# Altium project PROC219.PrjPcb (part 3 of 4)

## Sheet PROC219_PluckLock.SchDoc
size 431 x 279 mm; Date: Not shown in title block; ApprovedBy: Not shown in title block; CheckedBy: Not shown in title block; Author: Not shown in title block; CompanyName: Not shown in title block; Engineer: Not shown in title block; Organization: Not shown in title block; Address1: Not shown in title block; Address2: Not shown in title block; Address3: Not shown in title block; Address4: Not shown in title block; DocumentNumber: 2; Revision: Use project parameter SCH_Rev; SheetNumber: 9; SheetTotal: 16; PageSetup: Record=PageOptions¦CenterHorizontal=True¦CenterVertical=True¦PrintScale=1.00¦XCorrection=1.00¦YCorrection=1.00¦PrintKind=0¦BorderSize=5000000¦LeftOffset=0¦BottomOffset=0¦Orientation=2¦PaperLength=1000¦PaperWidth=1000¦Scale=100¦PaperSource=15¦PrintQuality=600¦MediaType=1¦DitherType=10¦PaperKind=Letter¦PrintScaleMode=1
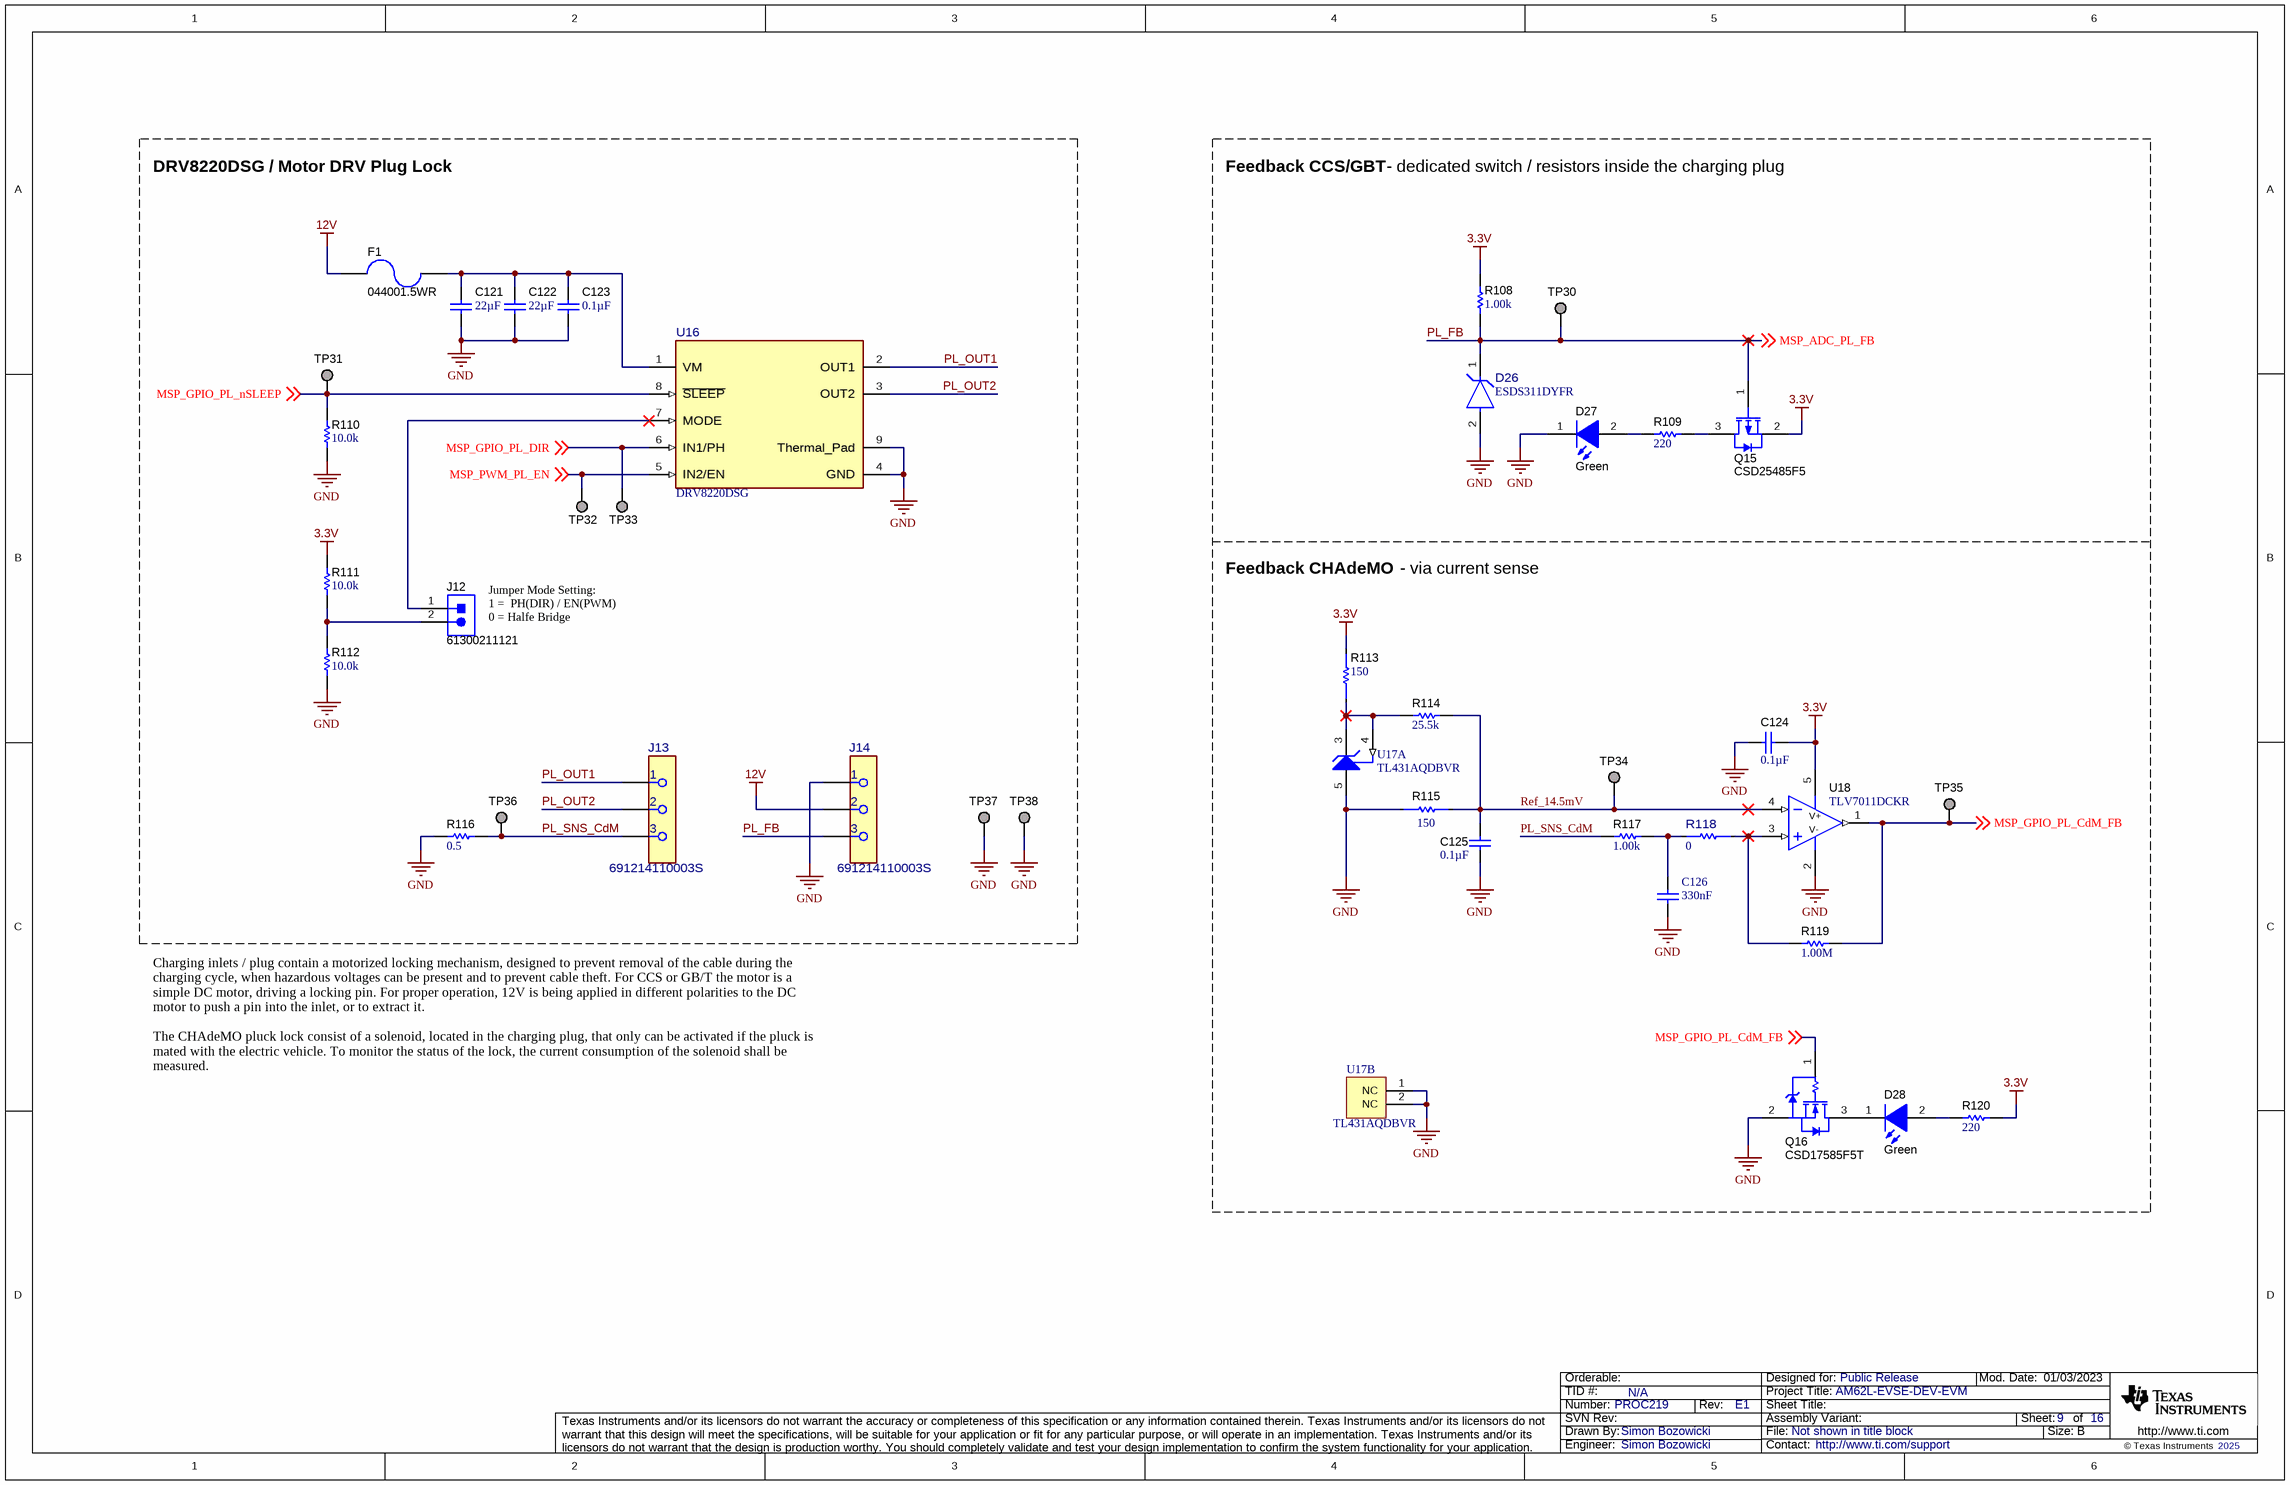
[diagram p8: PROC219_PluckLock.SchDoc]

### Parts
C121  ValueDisplayed: 22µF  [1210_270]  (hidden comment: CC1210KKX7R8BB226)
C122  ValueDisplayed: 22µF  [1210_270]  (hidden comment: CC1210KKX7R8BB226)
C123  ValueDisplayed: 0.1µF  [0402]  (hidden comment: CC0402KRX7R8BB104)
C124  ValueDisplayed: 0.1µF  [0402]  (hidden comment: CC0402KRX7R8BB104)
C125  ValueDisplayed: 0.1µF  [0402]  (hidden comment: CC0402KRX7R8BB104)
C126  value 330nF  [WCAP-CSGP_0603_L1.6W0.8H0.8_Reflow]  (hidden comment: 885012206121)
D26  ESDS311DYFR  [DYF0002A-MFG]
D27  value Green  [WL-SMCW_GREEN]  (hidden comment: 150060VS75000)
D28  value Green  [WL-SMCW_GREEN]  (hidden comment: 150060VS75000)
F1  044001.5WR  [1206]
J12  61300211121  [WURTH_61300211121]
J13  691214110003S  [FP-691214110003S_CONN_TERM_BLK_3-MFG]
J14  691214110003S  [FP-691214110003S_CONN_TERM_BLK_3-MFG]
Q15  CSD25485F5  [YJK0003A]
Q16  CSD17585F5T  [YJK0003A]
R108  ValueDisplayed: 1.00k  [0402]  (hidden comment: RC0402FR-071KL)
R109  ValueDisplayed: 220  [0402]  (hidden comment: CRCW0402220RJNED)
R110  ValueDisplayed: 10.0k  [0402]  (hidden comment: ERJ-2RKF1002X)
R111  ValueDisplayed: 10.0k  [0402]  (hidden comment: ERJ-2RKF1002X)
R112  ValueDisplayed: 10.0k  [0402]  (hidden comment: ERJ-2RKF1002X)
R113  value 150  [FP-TNPW0402150RBEED_0402-MFG]  (hidden comment: TNPW0402150RBEED)
R114  ValueDisplayed: 25.5k  [0402]  (hidden comment: CRCW040225K5FKED)
R115  value 150  [FP-TNPW0402150RBEED_0402-MFG]  (hidden comment: TNPW0402150RBEED)
R116  ValueDisplayed: 0.5  [2512]  (hidden comment: CSRN2512FKR500)
R117  ValueDisplayed: 1.00k  [0402]  (hidden comment: RC0402FR-071KL)
R118  value 0  [FP-CRG0402ZR_0402-IPC_C]  (hidden comment: CRG0402ZR)
R119  ValueDisplayed: 1.00M  [0402]  (hidden comment: RC0402FR-071ML)
R120  ValueDisplayed: 220  [0402]  (hidden comment: CRCW0402220RJNED)
TP30  TP_SM_1MM  [TP_SM_1MM]  (value not drawn)  (no BOM)
TP31  TP_SM_1MM  [TP_SM_1MM]  (value not drawn)  (no BOM)
TP32  TP_SM_1MM  [TP_SM_1MM]  (value not drawn)  (no BOM)
TP33  TP_SM_1MM  [TP_SM_1MM]  (value not drawn)  (no BOM)
TP34  TP_SM_1MM  [TP_SM_1MM]  (value not drawn)  (no BOM)
TP35  TP_SM_1MM  [TP_SM_1MM]  (value not drawn)  (no BOM)
TP36  TP_SM_1MM  [TP_SM_1MM]  (value not drawn)  (no BOM)
TP37  TP_SM_1MM  [TP_SM_1MM]  (value not drawn)  (no BOM)
TP38  TP_SM_1MM  [TP_SM_1MM]  (value not drawn)  (no BOM)
U16  PartNumber: DRV8220DSG  [DSG0008A-MFG]  (hidden comment: DRV8220DSGR)
U17  TL431AQDBVR  [DBV0005A_N]  (parts A,B of 2)
U18  TLV7011DCKR  [DCK0005A_N]

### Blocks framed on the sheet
DRV8220DSG / Motor DRV Plug Lock: C121-C123 F1 J12-J14 R110-R112 R116 TP31-TP33 TP36-TP38 U16

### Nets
3.3V: C124.2 Q15.2(S) R108.2 R111.1 R113.2 R120.2 U18.5(V+)
12V: F1.2 J14.2
GND: C121.1 C122.1 C123.2 C124.1 C125.2 C126.1 D26.2(GND) D27.1(K) J14.1 Q16.2(S) R110.2 R112.2 R115.1 R116.2 TP37.1 TP38.1 U16.4(GND) U16.9(Thermal_Pad) U17.1(NC) U17.2(NC) U17.5(ANODE) U18.2(V-)
MSP_GPIO_PL_CdM_FB: Q16.1(G) R119.2 TP35.1 U18.1(OUT) ; off-sheet MSP_GPIO_PL_CdM_FB
MSP_GPIO_PL_DIR: TP33.1 U16.6(IN1/PH) ; off-sheet MSP_GPIO_PL_DIR
MSP_GPIO_PL_nSLEEP: R110.1 TP31.1 U16.8(~{SLEEP}) ; off-sheet MSP_GPIO_PL_nSLEEP
MSP_PWM_PL_EN: TP32.1 U16.5(IN2/EN) ; off-sheet MSP_PWM_PL_EN
PL_FB: D26.1(I/O) J14.3 Q15.1(G) R108.1 TP30.1 ; off-sheet MSP_ADC_PL_FB  [also labelled MSP_ADC_PL_FB]
PL_OUT1: J13.1 U16.2(OUT1)
PL_OUT2: J13.2 U16.3(OUT2)
PL_SNS_CdM: J13.3 R116.1 R117.2 TP36.1
Ref_14.5mV: C125.1 R114.2 R115.2 TP34.1 U18.4(IN-)
NetC121_2: C121.2 C122.2 C123.1 F1.1 U16.1(VM)
NetC126_2: C126.2 R117.1 R118.2
NetD27_2: D27.2(A) R109.1
NetD28_1: D28.1(K) Q16.3(D)
NetD28_2: D28.2(A) R120.1
NetJ12_1: J12.1 U16.7(MODE)
NetJ12_2: J12.2 R111.2 R112.1
NetQ15_3: Q15.3(D) R109.2
NetR113_1: R113.1 R114.1 U17.3(CATHODE) U17.4(REF)
NetR118_1: R118.1 R119.1 U18.3(IN+)

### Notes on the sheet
- Feedback CCS/GBT
- - dedicated switch / resistors inside the charging plug
- Feedback CHAdeMO
- - via current sense
- (near J12) Jumper Mode Setting:
  1 =  PH(DIR) / EN(PWM)
  0 = Halfe Bridge
- Charging inlets / plug contain a motorized locking mechanism, designed to prevent removal of the cable during the charging cycle, when hazardous voltages can be present and to prevent cable theft. For CCS or GB/T the motor is a simple DC motor, driving a locking pin. For proper operation, 12V is being applied in different polarities to the DC motor to push a pin into the inlet, or to extract it.
  The CHAdeMO pluck lock consist of a solenoid, located in the charging plug, that only can be activated if the pluck is mated with the electric vehicle. To monitor the status of the lock, the current consumption of the solenoid shall be measured.

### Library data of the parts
C121 C122 = CMP-0082267-1: CAP, CERM, 22 µF, 25 V,+/- 10%, X7R, 1210; Manufacturer: Yageo; TaMin_C: -55°C; ESR_ohm: 1m; Polarized: N; SizeAreaWB_mm2: 14.7; Value1: 0.001 ohm; U/M: EA; Value: 22uF; TaMax_C: 125°C; SizeZ_mm: 2.7; SizeX_mm: 3.2; SizeY_mm: 2.5; Cap_Case: 1210; Value2: 25V; SizeArea_mm2: 8; AEC Category: Q200
C123-C125 = CMP-0860555-1: CAP, CERM, 0.1 µF, 25 V,+/- 10%, X7R, 0402; Manufacturer: Yageo; SizeArea_mm2: 0.5; AEC Qualified: N; SizeX_mm: 1; U/M: EA; Value: 0.1uF; TaMin_C: -55°C; VDC_V: 25V; SizeZ_mm: 0.6; Cap_F: 100nF; TaMax_C: 125°C; SizeAreaWB_mm2: 3; AEC Category: Q200
C126 = CMP-0115492-1: WCAP-CSGP Multilayer Ceramic Chip Capacitor, General Purpose, size 0603, X7R, 330nF, 50VDC; Manufacturer: Wurth Elektronik; Capacitance Tolerance: +/-10%; Dissipation Factor: 10%; Insulation Resistance: 1.5GOhm; Rated Voltage (DC): 50V; Technical Reference: X7R0603334K050DFCT10000
D26 = CMP-0122929-1: One-channel unidirectional device for 3.3V surge protection in SOD-323 package; Manufacturer: Texas Instruments; SizeZ_mm: 1mm; AEC Qualified: No; Breakdown Voltage: 4.5V; Cap_F: 4.5pF; Clamping Voltage: 6.3V; Ipp: 25A; Number Of Channels: 1; Ppk: 170W; Standoff Height: 0mm; TaMax_C: +125°C; TaMin_C: -40°C; VRWM: 3.6V
D27 D28 = CMP-0002894-2: LED, Green, SMD; Manufacturer: Wurth Elektronik; Type: AlInGaP; Value2: 2V; Io_A: 20mA; Value1: W
F1 = CMP-0003461-2: Fuse, 1.5 A, 50VAC/VDC, SMD; Manufacturer: Littelfuse; Irating_A: 1.5A; SizeAreaWB_mm2: 10.92; Interrupt_AC: 50A; VAC_V: 50V; SizeZ_mm: 1.35; SizeX_mm: 3.2; SizeY_mm: 1.6; SizeArea_mm2: 5.12; Rtyp_Ohm: 0.1759; MeltingTyp: 0.50652
J12 = CMP-0054794-2: Header, 2.54 mm, 2x1, Gold, TH; Manufacturer: Wurth Elektronik; Shrouded: N; Gender: Male; Green_REACh: Passed; Pitch_mm: 2.54; Green_Lifecycle: Active; Row_Count: 1; Cert_UL: Y
J13 J14 = CMP-0124724-1: 3 Position Wire to Board Terminal Block Horizontal with Board 0.138" (3.50mm) Through Hole; Manufacturer: Wurth; ContactFinish: Tin,Nickel; Current_A: 10A; Row_Count: 1; Voltage_V: 300V; AEC Qualified: No; Conn Gender: Female; DUT-Pitch_mm: 3.5mm; Is Female: yes; Max Wire Gauge: 16; Min Wire Gauge: 30; SizeZ_mm: 9.2mm
Q15 = CMP-0000031-3: MOSFET, P-CH, -20 V, -5.3 A, YJK0003A (PICOSTAR-3); Manufacturer: Texas Instruments; Alternate Manufacturer: None; SizeZ_mm: 0.35; SizeX_mm: 1.49; ChType: P; Vgs_V: -12V; Value2: 2.7 nC; SizeArea_mm2: 1.0877; QgTyp_nC: 2.7; SizeY_mm: 0.73; AEC Category: Q101; IdsMax_A: -5.3A; AEC Qualified: N; Value: -20V; SizeAreaWB_mm2: 4.3077; ChMode: Enhancement
Q16 = CMP-0067551-1: MOSFET, N-CH, 30 V, 5.9 A, YJK0003A (PICOSTAR-3); Alternate Manufacturer: None; Manufacturer: Texas Instruments; Rdson45_ohm: 0.033; QgTyp_nC: 1.9; SizeAreaWB_mm2: 4.3077; Vgs_V: 20V; Value1: 0.033 ohm; VdsMax_V: 30V; U/M: EA; Value: 30V; IdsMax_A: 5.9A; SizeZ_mm: 0.35; SizeX_mm: 1.49; SizeY_mm: 0.73; Value2: 1.9 nC; SizeArea_mm2: 1.0877; ChType: N; AEC Category: Q101
R108 R117 = CMP-0026725-1: RES, 1.00 k, 1%, 0.0625 W, 0402; Manufacturer: Yageo America; Power_W: 62.5mW; TempCo: 100 ppm/C; Value_Code: 1k00; U/M: EA; Value: 1.00k; EIA_Code: E96; Res_ohm: 1k; SizeX_mm: 1; SizeY_mm: 0.5; SizeZ_mm: 0.6; AEC Qualified: N; VDC_V: 50V; AEC Category: Q200
R109 R120 = CMP-0026878-3: RES, 220, 5%, 0.063 W, AEC-Q200 Grade 0, 0402; Manufacturer: Vishay-Dale; Power_W: 63mW; TempCo: 200 ppm/C; Value_Code: 220R; Value: 220; EIA_Code: E24; SizeX_mm: 1; SizeY_mm: 0.5; SizeZ_mm: 0.6; Value2: 0.063W; AEC Qualified: Y; VDC_V: 50V; AEC Category: Q200; AEC Grade: 0
R110-R112 = CMP-0026658-1: RES, 10.0 k, 1%, 0.1 W, 0402; Manufacturer: Panasonic; Power_W: 100mW; TempCo: 100 ppm/C; Value_Code: 10k0; U/M: EA; Value: 10.0k; EIA_Code: E96; Res_ohm: 10k; SizeX_mm: 1; SizeY_mm: 0.5; SizeZ_mm: 0.6; Value2: 0.1W; VDC_V: 50V; AEC Category: Q200
R113 R115 = CMP-0001694-1: 150 Ohms ±0.1% 0.063W, 1/16W Chip Resistor 0402 (1005 Metric) Anti-Sulfur, Automotive AEC-Q200, Moisture Resistant Thin Film; Manufacturer: Vishay Dale; AEC Grade: Grade 0; AEC Qualified: Yes; Power_W: 100mW; SizeZ_mm: 0.4mm; TempCo: 25ppm/°C; VDC_V: 50V
R114 = CMP-0026201-2: RES, 25.5 k, 1%, 0.063 W, AEC-Q200 Grade 0, 0402; Manufacturer: Vishay-Dale; Power_W: 63mW; TempCo: 100 ppm/C; Value_Code: 25k5; Value: 25.5k; EIA_Code: E96; SizeX_mm: 1; SizeY_mm: 0.5; SizeZ_mm: 0.6; Value2: 0.063W; AEC Qualified: Y; VDC_V: 50V; AEC Category: Q200; AEC Grade: 0
R116 = CMP-0015788-2: RES, 0.5, 1%, 2 W, 2512; Manufacturer: Stackpole Electronics Inc; Power_W: 2W; TempCo: 200 ppm/C; Value_Code: R500; U/M: EA; Value: 0.5; Res_ohm: 5d; SizeX_mm: 6.3; SizeY_mm: 3.2; SizeZ_mm: 0.71; SizeArea_mm2: 20.16; AEC Category: Q200
R118 = CMP-0095664-1: Jumper 0.063W, 1/16W Chip Resistor 0402 (1005 Metric) - Thick Film; Manufacturer: TE Connectivity; SizeZ_mm: 0.4mm; VDC_V: 50V; TempCo: 200ppm/°C; Power_W: 62.5mW; AEC Qualified: No
R119 = CMP-0026727-1: RES, 1.00 M, 1%, 0.063 W, 0402; Manufacturer: Yageo America; Power_W: 63mW; TempCo: 100 ppm/C; Value_Code: 1M00; U/M: EA; Value: 1.00Meg; EIA_Code: E96; Res_ohm: 1M; SizeX_mm: 1; SizeY_mm: 0.5; SizeZ_mm: 0.6; Value2: 0.063W; AEC Category: Q200
TP30-TP38 = CMP-0003825-1: 1mm Test Point, SMT; Manufacturer: Any
U16 = CMP-0090279-2: 1.6A H-bridge motor driver, PWM, PH/EN, ½ bridge control, with low power sleep mode; Manufacturer: Texas Instruments; Number Of Outputs: 2; Standoff Height: 0mm; TaMin_C: -40°C; Max Supply Voltage: 18V; TJmax_C: +150°C; Motor Type: Brushed; Min Supply Voltage: 4.5V; TaMax_C: +125°C; Switching Frequency: 100kHz; AEC Qualified: No; SizeZ_mm: 0.8mm; CompType: IC; AEC Category: Q200
U17 = CMP-0032940-1: Adjustable Precision Shunt Regulator, 34 ppm / degC, 100 mA, -40 to 125 degC, 5-pin SOT-23 (DBV), Green (RoHS & no Sb/Br); Manufacturer: Texas Instruments; Min Iz for Regulation(uA): 600; Rating: Catalog; SubFamily: Shunt Voltage Reference; Temp Coeff(Typ)(ppm/ degree C): 34; Iout/Iz(Max)(mA): 100; Temp Coeff(Max)(ppm/ degree C): 92; VO Adj(Min)(V): 2.495; VO Adj(Max)(V): 36; Initial Accuracy @ 25/deg C(%): 1
U18 = CMP-0860894-1: Low power, small size comparator with push-pull output, DCK0005A (SOT-SC70-5); Alternate Manufacturer: Texas Instruments; Alternate PartNumber: TLV7011DCKT; CompType: IC; SizeZ_mm: 1.1; SizeY_mm: 2; AEC Qualified: N; AEC Category: Q200; SizeX_mm: 2.1; SizeAreaWB_mm2: 9.3; SizeArea_mm2: 4.2; Rating: Catalog

## Sheet PROC219_Temp_Sense.SchDoc
size 431 x 279 mm; Date: Not shown in title block; ApprovedBy: Not shown in title block; CheckedBy: Not shown in title block; Author: Not shown in title block; CompanyName: Not shown in title block; Engineer: Not shown in title block; Organization: Not shown in title block; Address1: Not shown in title block; Address2: Not shown in title block; Address3: Not shown in title block; Address4: Not shown in title block; DocumentNumber: 1; Revision: Use project parameter SCH_Rev; SheetNumber: 10; SheetTotal: 16; PageSetup: Record=PageOptions¦CenterHorizontal=True¦CenterVertical=True¦PrintScale=1.00¦XCorrection=1.00¦YCorrection=1.00¦PrintKind=0¦BorderSize=5000000¦LeftOffset=0¦BottomOffset=0¦Orientation=2¦PaperLength=1000¦PaperWidth=1000¦Scale=100¦PaperSource=15¦PrintQuality=600¦MediaType=1¦DitherType=10¦PaperKind=Letter¦PrintScaleMode=1
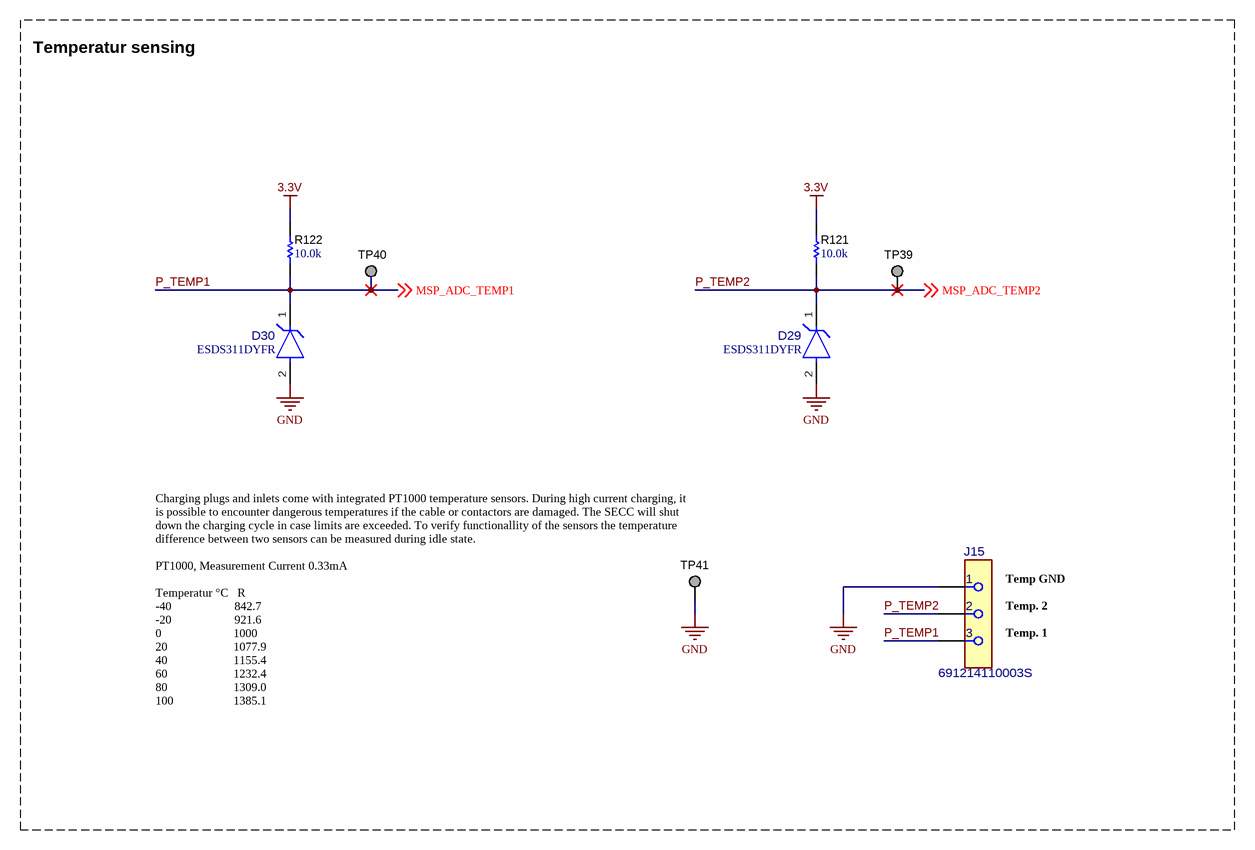
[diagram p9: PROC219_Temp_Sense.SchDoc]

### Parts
D29  ESDS311DYFR  [DYF0002A-MFG]
D30  ESDS311DYFR  [DYF0002A-MFG]
J15  691214110003S  [FP-691214110003S_CONN_TERM_BLK_3-MFG]
R121  ValueDisplayed: 10.0k  [0402]  (hidden comment: RT0402BRD0710KL)
R122  ValueDisplayed: 10.0k  [0402]  (hidden comment: RT0402BRD0710KL)
TP39  TP_SM_1MM  [TP_SM_1MM]  (value not drawn)  (no BOM)
TP40  TP_SM_1MM  [TP_SM_1MM]  (value not drawn)  (no BOM)
TP41  TP_SM_1MM  [TP_SM_1MM]  (value not drawn)  (no BOM)

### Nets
3.3V: R121.2 R122.2
GND: D29.2(GND) D30.2(GND) J15.1 TP41.1
P_TEMP1: D30.1(I/O) J15.3 R122.1 TP40.1 ; off-sheet MSP_ADC_TEMP1  [also labelled MSP_ADC_TEMP1]
P_TEMP2: D29.1(I/O) J15.2 R121.1 TP39.1 ; off-sheet MSP_ADC_TEMP2  [also labelled MSP_ADC_TEMP2]

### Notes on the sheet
- Temperatur sensing
- (near TP41) Charging plugs and inlets come with integrated PT1000 temperature sensors. During high current charging, it is possible to encounter dangerous temperatures if the cable or contactors are damaged. The SECC will shut down the charging cycle in case limits are exceeded. To verify functionallity of the sensors the temperature difference between two sensors can be measured during idle state.
- (near J15) Temp GND
- (near J15) Temp. 2
- (near J15) Temp. 1
- PT1000, Measurement Current 0.33mA
  Temperatur °C   R
  -40                     842.7
  -20                     921.6
  0                        1000
  20                      1077.9
  40                      1155.4
  60                      1232.4
  80                      1309.0
  100                    1385.1

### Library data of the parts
D29 D30 = CMP-0122929-1: as D26 on sheet PROC219_PluckLock
J15 = CMP-0124724-1: as J13 on sheet PROC219_PluckLock
R121 R122 = CMP-0065360-1: RES, 10.0 k, .1%, .0625 W, 0402; Manufacturer: Yageo America; Power_W: 62.5mW; TempCo: 25 ppm/C; Value_Code: 10k0; U/M: EA; Value: 10.0k; EIA_Code: E192; Tolerance_%: 0.1%; Res_ohm: 10k; SizeX_mm: 1.0; SizeY_mm: 0.5; SizeZ_mm: 0.6; Value2: .0625W; VDC_V: 50V; AEC Category: Q200
TP39-TP41 = CMP-0003825-1: 1mm Test Point, SMT; Manufacturer: Any

## Sheet PROC219_Serial.SchDoc
size 431 x 279 mm; Date: Not shown in title block; ApprovedBy: Not shown in title block; CheckedBy: Not shown in title block; Author: Not shown in title block; CompanyName: Not shown in title block; Engineer: Not shown in title block; Organization: Not shown in title block; Address1: Not shown in title block; Address2: Not shown in title block; Address3: Not shown in title block; Address4: Not shown in title block; DocumentNumber: 1; Revision: Use project parameter SCH_Rev; SheetNumber: 11; SheetTotal: 16; PageSetup: Record=PageOptions¦CenterHorizontal=True¦CenterVertical=True¦PrintScale=1.00¦XCorrection=1.00¦YCorrection=1.00¦PrintKind=0¦BorderSize=5000000¦LeftOffset=0¦BottomOffset=0¦Orientation=2¦PaperLength=1000¦PaperWidth=1000¦Scale=100¦PaperSource=15¦PrintQuality=600¦MediaType=1¦DitherType=10¦PaperKind=Letter¦PrintScaleMode=1
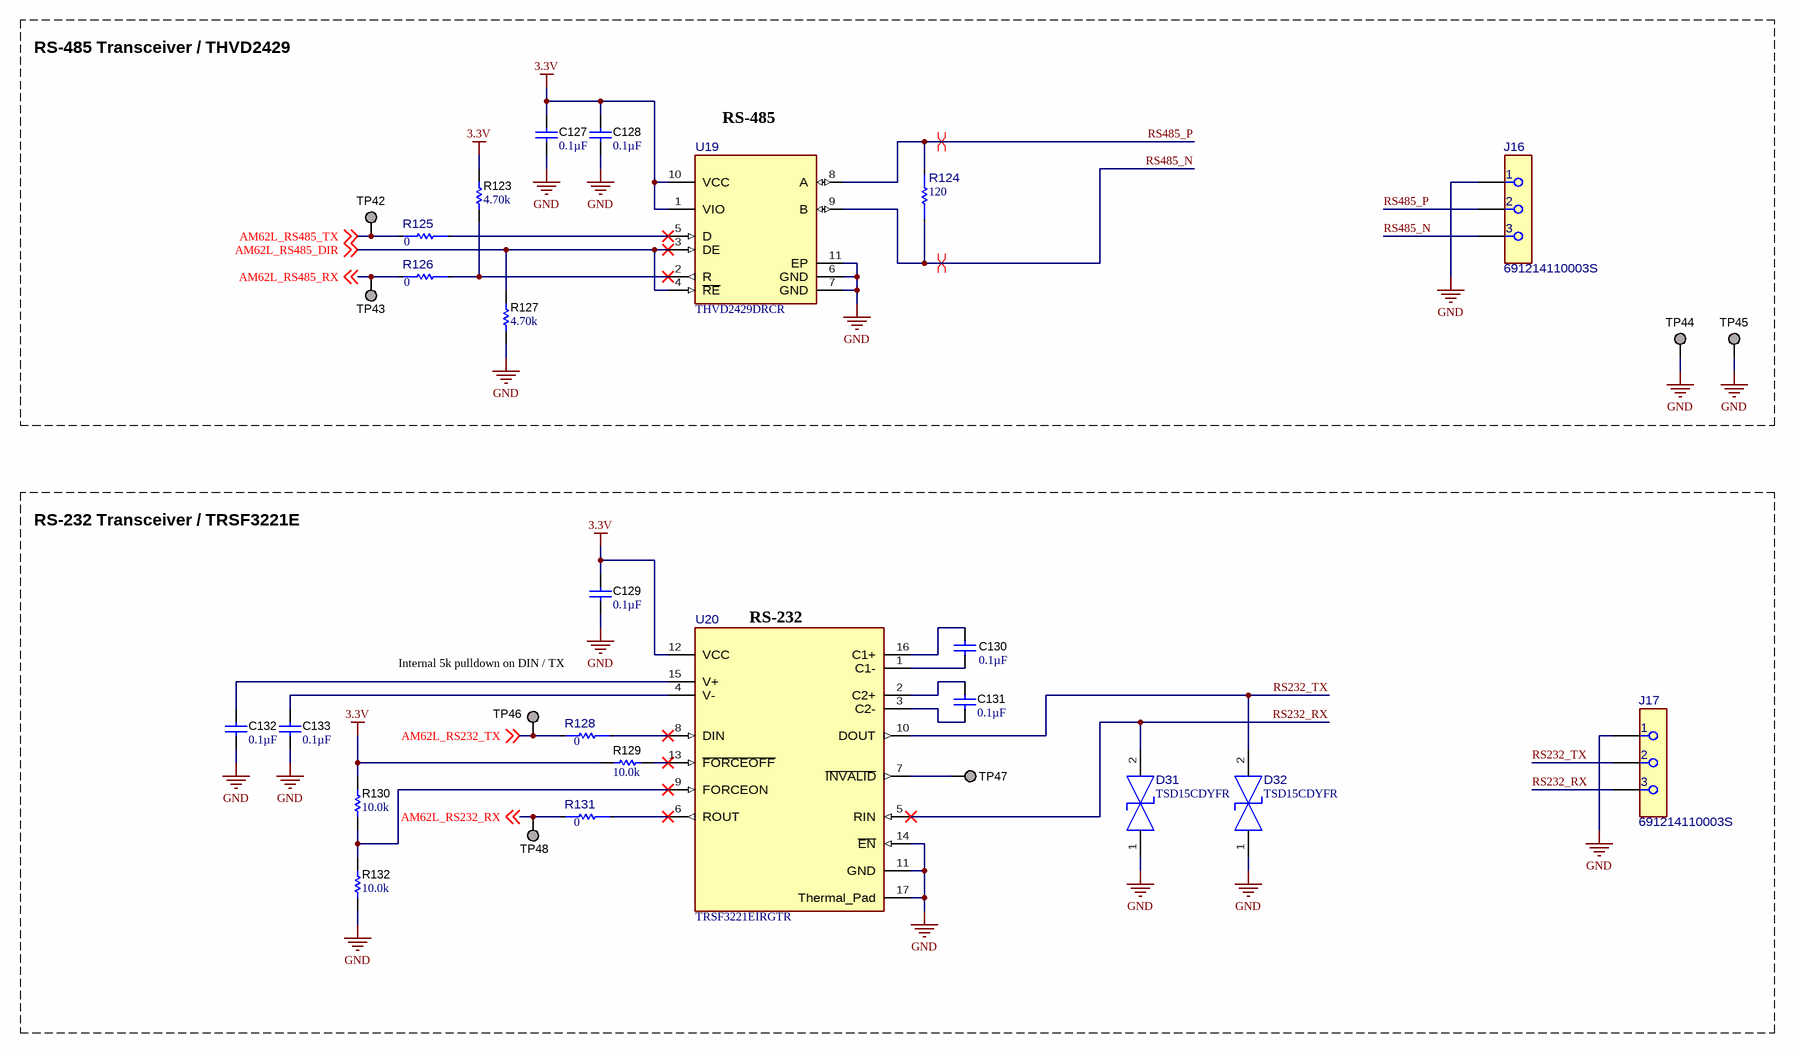
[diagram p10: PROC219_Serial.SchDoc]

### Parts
C127  ValueDisplayed: 0.1µF  [0402]  (hidden comment: CC0402KRX7R8BB104)
C128  ValueDisplayed: 0.1µF  [0402]  (hidden comment: CC0402KRX7R8BB104)
C129  ValueDisplayed: 0.1µF  [0402]  (hidden comment: CC0402KRX7R8BB104)
C130  ValueDisplayed: 0.1µF  [0402]  (hidden comment: CC0402KRX7R8BB104)
C131  ValueDisplayed: 0.1µF  [0402]  (hidden comment: CC0402KRX7R8BB104)
C132  ValueDisplayed: 0.1µF  [0402]  (hidden comment: CC0402KRX7R8BB104)
C133  ValueDisplayed: 0.1µF  [0402]  (hidden comment: CC0402KRX7R8BB104)
D31  PartNumber: TSD15CDYFR  [DYF0002A-CA-MFG]  (hidden comment: TSD15C)
D32  PartNumber: TSD15CDYFR  [DYF0002A-CA-MFG]  (hidden comment: TSD15C)
J16  691214110003S  [FP-691214110003S_CONN_TERM_BLK_3-MFG]
J17  691214110003S  [FP-691214110003S_CONN_TERM_BLK_3-MFG]
R123  ValueDisplayed: 4.70k  [0402]  (hidden comment: ERJ-2RKF4701X)
R124  value 120  [FP-SDR10EZPF1200_0805-MFG]  (hidden comment: SDR10EZPF1200)
R125  value 0  [FP-CRG0402ZR_0402-IPC_C]  (hidden comment: CRG0402ZR)
R126  value 0  [FP-CRG0402ZR_0402-IPC_C]  (hidden comment: CRG0402ZR)
R127  ValueDisplayed: 4.70k  [0402]  (hidden comment: ERJ-2RKF4701X)
R128  value 0  [FP-CRG0402ZR_0402-IPC_C]  (hidden comment: CRG0402ZR)
R129  ValueDisplayed: 10.0k  [0402]  (hidden comment: ERJ-2RKF1002X)
R130  ValueDisplayed: 10.0k  [0402]  (hidden comment: ERJ-2RKF1002X)
R131  value 0  [FP-CRG0402ZR_0402-IPC_C]  (hidden comment: CRG0402ZR)
R132  ValueDisplayed: 10.0k  [0402]  (hidden comment: ERJ-2RKF1002X)
TP42  TP_SM_1MM  [TP_SM_1MM]  (value not drawn)  (no BOM)
TP43  TP_SM_1MM  [TP_SM_1MM]  (value not drawn)  (no BOM)
TP44  TP_SM_1MM  [TP_SM_1MM]  (value not drawn)  (no BOM)
TP45  TP_SM_1MM  [TP_SM_1MM]  (value not drawn)  (no BOM)
TP46  TP_SM_1MM  [TP_SM_1MM]  (value not drawn)  (no BOM)
TP47  TP_SM_1MM  [TP_SM_1MM]  (value not drawn)  (no BOM)
TP48  TP_SM_1MM  [TP_SM_1MM]  (value not drawn)  (no BOM)
U19  THVD2429DRCR  [DRC0010V-MFG]
U20  TRSF3221EIRGTR  [RGT0016C-MFG]

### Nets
3.3V: C127.1 C128.1 C129.1 R123.2 R129.2 R130.1 U19.1(VIO) U19.10(VCC) U20.12(VCC)
GND: C127.2 C128.2 C129.2 C132.2 C133.2 D31.1(1_IO) D32.1(1_IO) J16.1 J17.1 R127.1 R132.2 TP44.1 TP45.1 U19.6(GND) U19.7(GND) U19.11(EP) U20.11(GND) U20.14(~{EN}) U20.17(Thermal_Pad)
AM62L_RS232_RX: R131.2 TP48.1 ; off-sheet AM62L_RS232_RX
AM62L_RS232_TX: R128.2 TP46.1 ; off-sheet AM62L_RS232_TX
AM62L_RS485_DIR: R127.2 U19.3(DE) U19.4(~{RE}) ; off-sheet AM62L_RS485_DIR
AM62L_RS485_RX: R126.2 TP43.1 ; off-sheet AM62L_RS485_RX
AM62L_RS485_TX: R125.2 TP42.1 ; off-sheet AM62L_RS485_TX
RS232_RX: D31.2(2_IO) J17.3 U20.5(RIN)
RS232_TX: D32.2(2_IO) J17.2 U20.10(DOUT)
RS485_N: J16.3 R124.1 U19.9(B)
RS485_P: J16.2 R124.2 U19.8(A)
NetC130_1: C130.1 U20.16(C1+)
NetC130_2: C130.2 U20.1(C1-)
NetC131_1: C131.1 U20.2(C2+)
NetC131_2: C131.2 U20.3(C2-)
NetC132_1: C132.1 U20.15(V+)
NetC133_1: C133.1 U20.4(V-)
NetR123_1: R123.1 R126.1 U19.2(R)
NetR125_1: R125.1 U19.5(D)
NetR128_1: R128.1 U20.8(DIN)
NetR129_1: R129.1 U20.13(~{FORCEOFF})
NetR130_2: R130.2 R132.1 U20.9(FORCEON)
NetR131_1: R131.1 U20.6(ROUT)
NetTP47_1: TP47.1 U20.7(~{INVALID})

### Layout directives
differential pair: RS485_N, RS485_P

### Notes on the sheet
- RS-485 Transceiver / THVD2429
- RS-485
- RS-232 Transceiver / TRSF3221E
- (near U20) RS-232
- Internal 5k pulldown on DIN / TX

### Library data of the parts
C127-C133 = CMP-0860555-1: as C123-C125 on sheet PROC219_PluckLock
D31 D32 = CMP-0124250-1: 15V 13A bidirectional surge-protection diode; Manufacturer: Texas Instruments; SizeZ_mm: 1mm; Standoff Height: 0mm
J16 J17 = CMP-0124724-1: as J13 on sheet PROC219_PluckLock
R123 R127 = CMP-0026700-1: RES, 4.70 k, 1%, 0.1 W, 0402; Manufacturer: Panasonic; Power_W: 100mW; TempCo: 100 ppm/C; Value_Code: 4k70; U/M: EA; Value: 4.70k; Res_ohm: 4.7k; SizeX_mm: 1; SizeY_mm: 0.5; SizeZ_mm: 0.6; Value2: 0.1W; VDC_V: 50V; AEC Category: Q200
R124 = CMP-0126832-1: Res Thick Film 0805 120 Ohm 1% 0.5W(1/2W) ±100ppm/C Pad SMD T/R Automotive; Manufacturer: Rohm; AEC Grade: Grade 0; AEC Qualified: Yes; Power_W: 660mW; SizeZ_mm: 0.65mm; TempCo: 100ppm/°C; VDC_V: 400V
R125 R126 R128 R131 = CMP-0095664-1: as R118 on sheet PROC219_PluckLock
R129 R130 R132 = CMP-0026658-1: as R110-R112 on sheet PROC219_PluckLock
TP42-TP48 = CMP-0003825-1: 1mm Test Point, SMT; Manufacturer: Any
U19 = CMP-0094911-1: 3-V to 5.5-V Small RS-485 Transceivers With Integrated 4-kV Surge Protection and High Bus-Fault Protection in Small Packages; Manufacturer: Texas Instruments; Number Of Transmitters: 1; Max Supply Voltage: 5.5V; Simplex Duplex: Half-Duplex; TJmax_C: +150°C; AEC Qualified: No; TaMax_C: +125°C; Standoff Height: 0mm; Data Rate: 20Mbits/s; Min Supply Voltage: 1.65V; SizeZ_mm: 1mm; TaMin_C: -40°C
U20 = CMP-0123242-1: 3- to 5.5-V single channel 1Mbps RS-232 line driver/receiver with +/-15-kV IEC-ESD protection; Manufacturer: Texas Instruments; SizeZ_mm: 1mm; AEC Qualified: No; Data Rate: 1Mbits/s; Max Supply Voltage: 5.5V; Min Supply Voltage: 3V; Nominal Supply Current: 0.3mA; Number Of Receivers: 1; Simplex Duplex: Full-Duplex; Standoff Height: 0mm; TaMax_C: +85°C; TaMin_C: -40°C; TJmax_C: +150°C

## Sheet PROC219_CAN.SchDoc
size 431 x 279 mm; Date: Not shown in title block; ApprovedBy: Not shown in title block; CheckedBy: Not shown in title block; Author: Not shown in title block; CompanyName: Not shown in title block; Engineer: Not shown in title block; Organization: Not shown in title block; Address1: Not shown in title block; Address2: Not shown in title block; Address3: Not shown in title block; Address4: Not shown in title block; DocumentNumber: 1; Revision: Use project parameter SCH_Rev; SheetNumber: 12; SheetTotal: 16; PageSetup: Record=PageOptions¦CenterHorizontal=True¦CenterVertical=True¦PrintScale=1.00¦XCorrection=1.00¦YCorrection=1.00¦PrintKind=0¦BorderSize=5000000¦LeftOffset=0¦BottomOffset=0¦Orientation=2¦PaperLength=1000¦PaperWidth=1000¦Scale=100¦PaperSource=15¦PrintQuality=600¦MediaType=1¦DitherType=10¦PaperKind=Letter¦PrintScaleMode=1
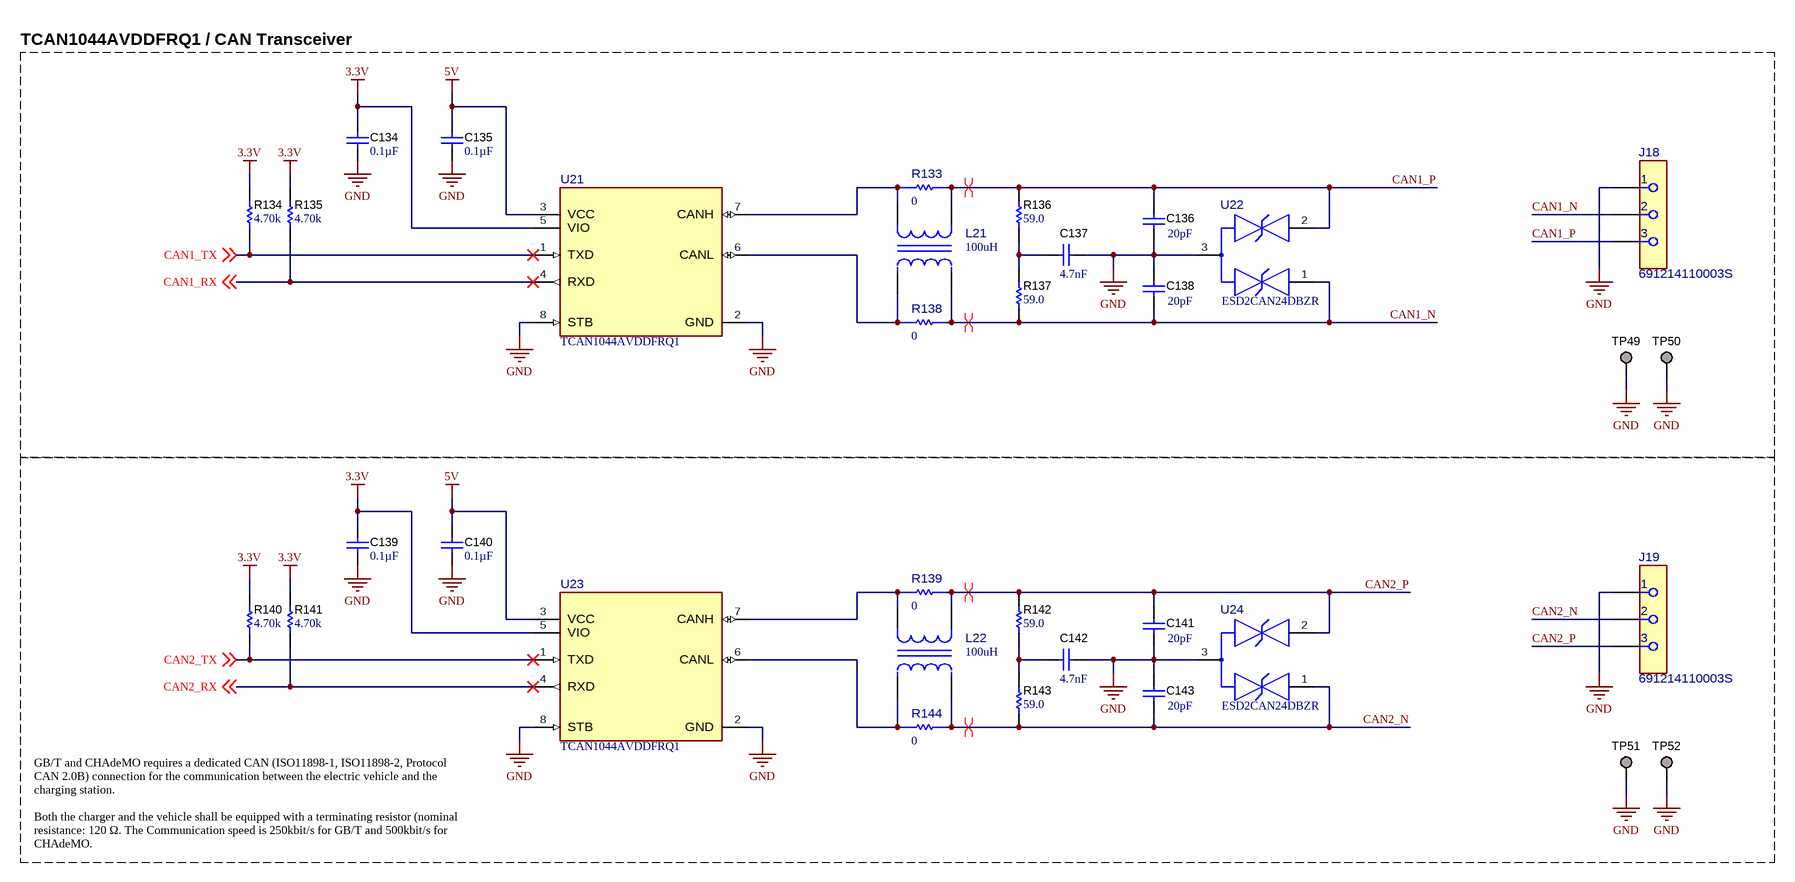
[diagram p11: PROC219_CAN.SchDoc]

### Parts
C134  ValueDisplayed: 0.1µF  [0402]  (hidden comment: CC0402KRX7R8BB104)
C135  ValueDisplayed: 0.1µF  [0402]  (hidden comment: CC0402KRX7R8BB104)
C136  ValueDisplayed: 20pF  [0402]  (hidden comment: C0402C200J5GACTU)
C137  value 4.7nF  [WCAP-CSGP_0402_L1W0.5H0.5]  (hidden comment: 885012205065)
C138  ValueDisplayed: 20pF  [0402]  (hidden comment: C0402C200J5GACTU)
C139  ValueDisplayed: 0.1µF  [0402]  (hidden comment: CC0402KRX7R8BB104)
C140  ValueDisplayed: 0.1µF  [0402]  (hidden comment: CC0402KRX7R8BB104)
C141  ValueDisplayed: 20pF  [0402]  (hidden comment: C0402C200J5GACTU)
C142  value 4.7nF  [WCAP-CSGP_0402_L1W0.5H0.5]  (hidden comment: 885012205065)
C143  ValueDisplayed: 20pF  [0402]  (hidden comment: C0402C200J5GACTU)
J18  691214110003S  [FP-691214110003S_CONN_TERM_BLK_3-MFG]
J19  691214110003S  [FP-691214110003S_CONN_TERM_BLK_3-MFG]
L21  value 100uH  [FP-ACT45B-101-2P-TL003_SMT_4MM5_3MM2-MFG]  (hidden comment: ACT45B-101-2P-TL003)
L22  value 100uH  [FP-ACT45B-101-2P-TL003_SMT_4MM5_3MM2-MFG]  (hidden comment: ACT45B-101-2P-TL003)
R133  value 0  [FP-CRCW12060000Z0EAC_1206-MFG]  (hidden comment: CRCW12060000Z0EAC)
R134  ValueDisplayed: 4.70k  [0402]  (hidden comment: ERJ-2RKF4701X)
R135  ValueDisplayed: 4.70k  [0402]  (hidden comment: ERJ-2RKF4701X)
R136  ValueDisplayed: 59.0  [1206]  (hidden comment: CRCW120659R0FKEA)
R137  ValueDisplayed: 59.0  [1206]  (hidden comment: CRCW120659R0FKEA)
R138  value 0  [FP-CRCW12060000Z0EAC_1206-MFG]  (hidden comment: CRCW12060000Z0EAC)
R139  value 0  [FP-CRCW12060000Z0EAC_1206-MFG]  (hidden comment: CRCW12060000Z0EAC)
R140  ValueDisplayed: 4.70k  [0402]  (hidden comment: ERJ-2RKF4701X)
R141  ValueDisplayed: 4.70k  [0402]  (hidden comment: ERJ-2RKF4701X)
R142  ValueDisplayed: 59.0  [1206]  (hidden comment: CRCW120659R0FKEA)
R143  ValueDisplayed: 59.0  [1206]  (hidden comment: CRCW120659R0FKEA)
R144  value 0  [FP-CRCW12060000Z0EAC_1206-MFG]  (hidden comment: CRCW12060000Z0EAC)
TP49  TP_SM_1MM  [TP_SM_1MM]  (value not drawn)  (no BOM)
TP50  TP_SM_1MM  [TP_SM_1MM]  (value not drawn)  (no BOM)
TP51  TP_SM_1MM  [TP_SM_1MM]  (value not drawn)  (no BOM)
TP52  TP_SM_1MM  [TP_SM_1MM]  (value not drawn)  (no BOM)
U21  TCAN1044AVDDFRQ1  [DDF0008A-MFG]
U22  ESD2CAN24DBZR  [DBZ0003A-MFG]
U23  TCAN1044AVDDFRQ1  [DDF0008A-MFG]
U24  ESD2CAN24DBZR  [DBZ0003A-MFG]

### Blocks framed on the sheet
TCAN1044AVDDFRQ1 / CAN Transceiver: C134-C138 J18 L21 R133-R138 TP49 TP50 U21 U22

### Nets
3.3V: C134.1 C139.1 R134.2 R135.2 R140.2 R141.2 U21.5(VIO) U23.5(VIO)
5V: C135.1 C140.1 U21.3(VCC) U23.3(VCC)
GND: C134.2 C135.2 C136.2 C137.2 C138.1 C139.2 C140.2 C141.2 C142.2 C143.1 J18.1 J19.1 TP49.1 TP50.1 TP51.1 TP52.1 U21.2(GND) U21.8(STB) U22.3(GND) U23.2(GND) U23.8(STB) U24.3(GND)
CAN1_N: C138.2 J18.2 L21.3 R137.1 R138.2 U22.1(1_IO)
CAN1_P: C136.1 J18.3 L21.4 R133.2 R136.2 U22.2(2_IO)
CAN1_RX: R135.1 U21.4(RXD) ; off-sheet CAN1_RX
CAN1_TX: R134.1 U21.1(TXD) ; off-sheet CAN1_TX
CAN2_N: C143.2 J19.2 L22.3 R143.1 R144.2 U24.1(1_IO)
CAN2_P: C141.1 J19.3 L22.4 R139.2 R142.2 U24.2(2_IO)
CAN2_RX: R141.1 U23.4(RXD) ; off-sheet CAN2_RX
CAN2_TX: R140.1 U23.1(TXD) ; off-sheet CAN2_TX
NetC137_1: C137.1 R136.1 R137.2
NetC142_1: C142.1 R142.1 R143.2
NetL21_1: L21.1 R133.1 U21.7(CANH)
NetL21_2: L21.2 R138.1 U21.6(CANL)
NetL22_1: L22.1 R139.1 U23.7(CANH)
NetL22_2: L22.2 R144.1 U23.6(CANL)

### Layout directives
differential pair: CAN1_N, CAN1_P, CAN2_N, CAN2_P

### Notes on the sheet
- GB/T and CHAdeMO requires a dedicated CAN (ISO11898-1, ISO11898-2, Protocol CAN 2.0B) connection for the communication between the electric vehicle and the charging station.
  Both the charger and the vehicle shall be equipped with a terminating resistor (nominal resistance: 120 Ω. The Communication speed is 250kbit/s for GB/T and 500kbit/s for CHAdeMO.

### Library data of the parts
C134 C135 C139 C140 = CMP-0860555-1: as C123-C125 on sheet PROC219_PluckLock
C136 C138 C141 C143 = CMP-0006241-2: CAP, CERM, 20 pF, 50 V, +/- 5%, C0G/NP0, 0402; Manufacturer: Kemet; TaMin_C: -55°C; Polarized: N; SizeAreaWB_mm2: 3; Value1: Unknown; U/M: EA; Value: 20pF; TaMax_C: 125°C; SizeZ_mm: 0.6; SizeX_mm: 1; SizeY_mm: 0.5; Value2: 50V; AEC Category: Q200
C137 C142 = CMP-0115376-1: WCAP-CSGP Multilayer Ceramic Chip Capacitor, General Purpose, size 0402, X7R, 4.7nF, 50VDC; Manufacturer: Wurth Elektronik; Capacitance Tolerance: +/-10%; Dissipation Factor: 2.5%; Insulation Resistance: 10GOhm; Rated Voltage (DC): 50V; Technical Reference: X7R0402472K050DFCT10000
J18 J19 = CMP-0124724-1: as J13 on sheet PROC219_PluckLock
L21 L22 = CMP-0084086-1: 100µH @ 100kHz 2 Line Common Mode Choke Surface Mount 5.8 kOhms @ 10MHz 150mA DCR 2Ohm; Manufacturer: TDK; AEC Grade: Grade 0; Tolerance_%: +50/-30%; AEC Qualified: Yes; SizeZ_mm: 3mm; DCR_ohm: 2Ω; Impedance At Frequency: 5800Ω @ 10MHz; Imax_A: 0.15A
R133 R138 R139 R144 = CMP-0094724-1: Jumper 0.25W, 1/4W Chip Resistor 1206 (3216 Metric) - Thick Film; Manufacturer: Vishay; SizeZ_mm: 0.65mm; Power_W: 250mW; VDC_V: 200V; AEC Qualified: No
R134 R135 R140 R141 = CMP-0026700-1: as R123 on sheet PROC219_Serial
R136 R137 R142 R143 = CMP-0017077-3: RES, 59.0, 1%, 0.25 W, AEC-Q200 Grade 0, 1206; Manufacturer: Vishay-Dale; Power_W: 250mW; TempCo: 100 ppm/C; Value_Code: 59R0; Value: 59.0; EIA_Code: E96; Res_ohm: 59; SizeX_mm: 3.2; SizeY_mm: 1.6; SizeZ_mm: 1.35; Value2: 0.25W; SizeArea_mm2: 5.12; AEC Qualified: Y; VDC_V: 200V; AEC Category: Q200; AEC Grade: 0
TP49-TP52 = CMP-0003825-1: 1mm Test Point, SMT; Manufacturer: Any
U21 U23 = CMP-0122870-1: Enhanced automotive CAN transceiver with standby and 1.8-V I/O support 8-SOT-23-THIN -40 to 150; Manufacturer: Texas Instruments; SizeZ_mm: 1.1mm; AEC Qualified: Yes; AEC Grade: Grade 1; Max Supply Voltage: 5.5V; Min Supply Voltage: 1.7V; Standoff Height: 0mm; TJmax_C: +150°C
U22 U24 = CMP-0093261-1: 24-V, 2-Channel ESD Protection Diode for In-Vehicle Networks; Manufacturer: Texas Instruments; Cap_F: 3pF; Breakdown Voltage: 25.5V; Clamping Voltage: 32V; TaMax_C: +150°C; Direction: Bidirectional; TaMin_C: -55°C; Ipp: 3.5A; VRWM: 24V; Standoff Height: 0.01mm; SizeZ_mm: 1.12mm; Ppk: 147W; AEC Qualified: No; Number Of Channels: 2

## Sheet PROC219_IO.SchDoc
size 431 x 279 mm; Date: Not shown in title block; ApprovedBy: Not shown in title block; CheckedBy: Not shown in title block; Author: Not shown in title block; CompanyName: Not shown in title block; Engineer: Not shown in title block; Organization: Not shown in title block; Address1: Not shown in title block; Address2: Not shown in title block; Address3: Not shown in title block; Address4: Not shown in title block; DocumentNumber: 1; Revision: Use project parameter SCH_Rev; SheetNumber: 13; SheetTotal: 16; PageSetup: Record=PageOptions¦CenterHorizontal=True¦CenterVertical=True¦PrintScale=1.00¦XCorrection=1.00¦YCorrection=1.00¦PrintKind=0¦BorderSize=5000000¦LeftOffset=0¦BottomOffset=0¦Orientation=2¦PaperLength=1000¦PaperWidth=1000¦Scale=100¦PaperSource=15¦PrintQuality=600¦MediaType=1¦DitherType=10¦PaperKind=Letter¦PrintScaleMode=1
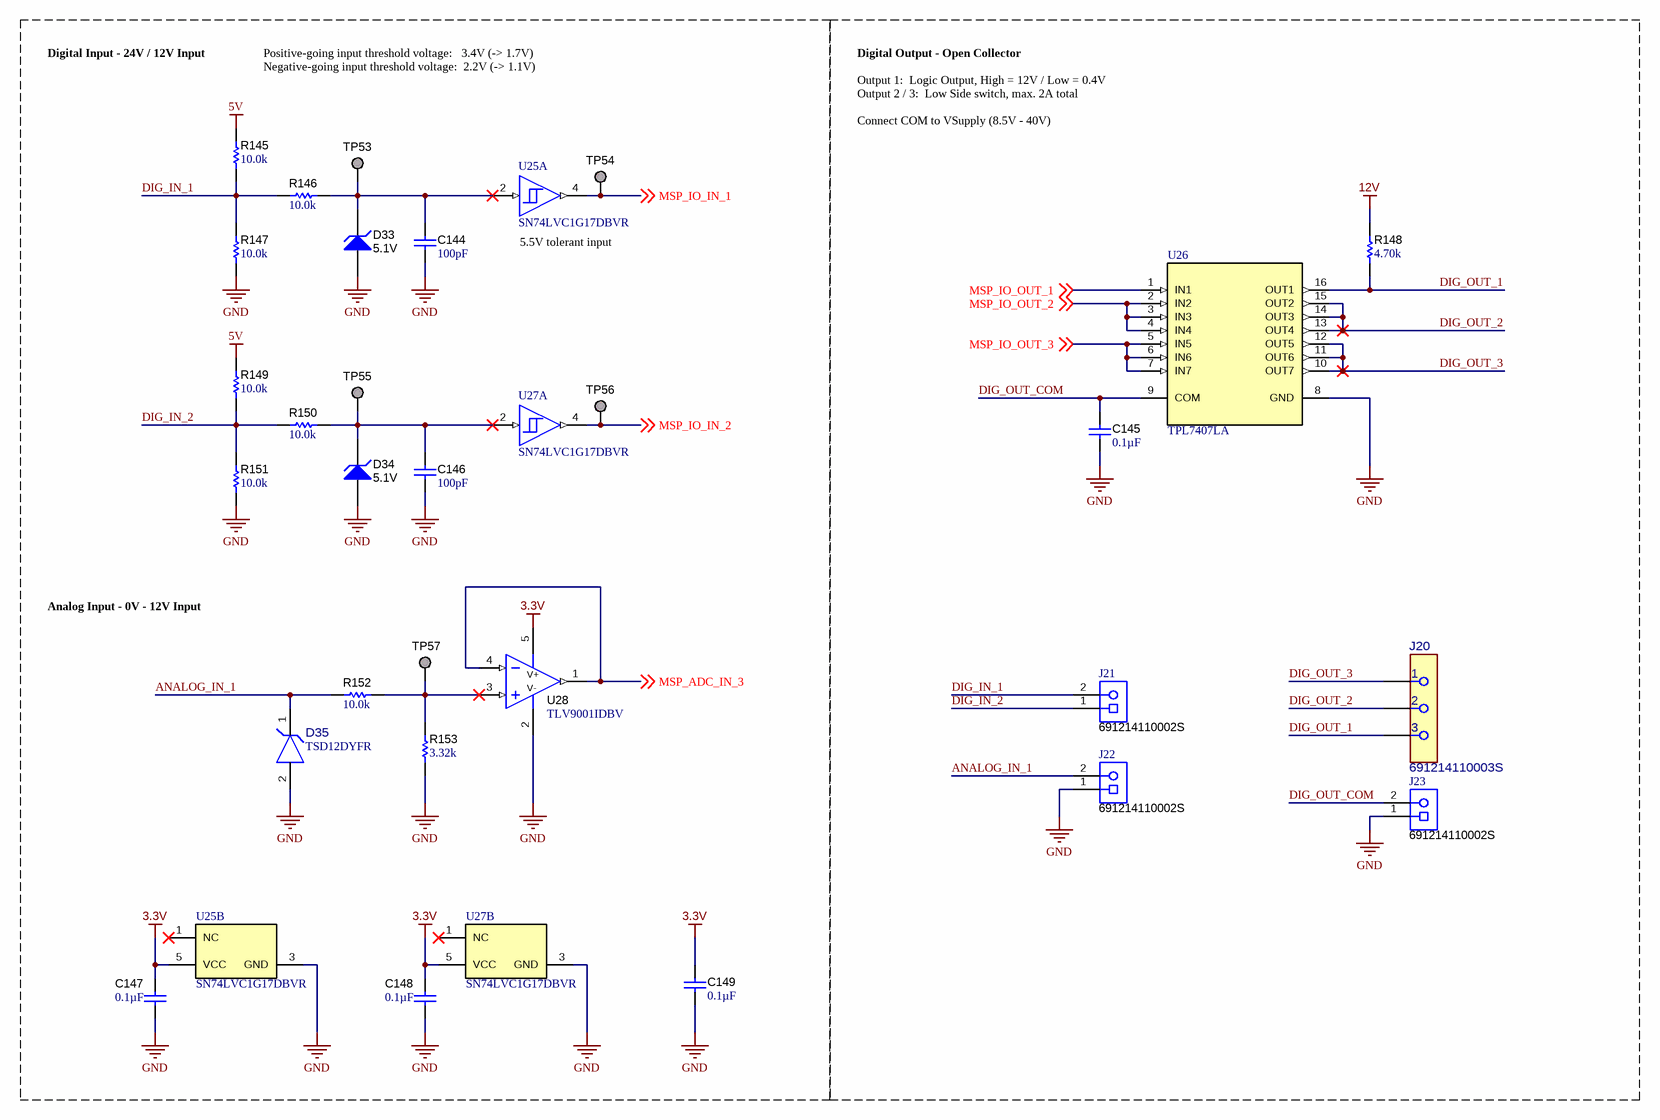
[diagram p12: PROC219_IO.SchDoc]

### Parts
C144  ValueDisplayed: 100pF  [0402]  (hidden comment: 04025A101FAT2A)
C145  ValueDisplayed: 0.1µF  [0402]  (hidden comment: CC0402KRX7R8BB104)
C146  ValueDisplayed: 100pF  [0402]  (hidden comment: 04025A101FAT2A)
C147  ValueDisplayed: 0.1µF  [0402]  (hidden comment: CC0402KRX7R8BB104)
C148  ValueDisplayed: 0.1µF  [0402]  (hidden comment: CC0402KRX7R8BB104)
C149  ValueDisplayed: 0.1µF  [0402]  (hidden comment: CC0402KRX7R8BB104)
D33  value 5.1V  [SOD-523]  (hidden comment: BZT52C5V1T-7)
D34  value 5.1V  [SOD-523]  (hidden comment: BZT52C5V1T-7)
D35  TSD12DYFR  [DYF0002A-MFG]
J20  691214110003S  [FP-691214110003S_CONN_TERM_BLK_3-MFG]
J21  691214110002S  [FP-691214110002S_HDR2-MFG]
J22  691214110002S  [FP-691214110002S_HDR2-MFG]
J23  691214110002S  [FP-691214110002S_HDR2-MFG]
R145  ValueDisplayed: 10.0k  [0402]  (hidden comment: ERJ-2RKF1002X)
R146  ValueDisplayed: 10.0k  [0402]  (hidden comment: ERJ-2RKF1002X)
R147  ValueDisplayed: 10.0k  [0402]  (hidden comment: ERJ-2RKF1002X)
R148  ValueDisplayed: 4.70k  [0402]  (hidden comment: ERJ-2RKF4701X)
R149  ValueDisplayed: 10.0k  [0402]  (hidden comment: ERJ-2RKF1002X)
R150  ValueDisplayed: 10.0k  [0402]  (hidden comment: ERJ-2RKF1002X)
R151  ValueDisplayed: 10.0k  [0402]  (hidden comment: ERJ-2RKF1002X)
R152  ValueDisplayed: 10.0k  [0402]  (hidden comment: RT0402BRD0710KL)
R153  ValueDisplayed: 3.32k  [0402]  (hidden comment: CRCW04023K32FKED)
TP53  TP_SM_1MM  [TP_SM_1MM]  (value not drawn)  (no BOM)
TP54  TP_SM_1MM  [TP_SM_1MM]  (value not drawn)  (no BOM)
TP55  TP_SM_1MM  [TP_SM_1MM]  (value not drawn)  (no BOM)
TP56  TP_SM_1MM  [TP_SM_1MM]  (value not drawn)  (no BOM)
TP57  TP_SM_1MM  [TP_SM_1MM]  (value not drawn)  (no BOM)
U25  SN74LVC1G17DBVR  [DBV0005A_N]  (parts A,B of 2)
U26  PartNumber: TPL7407LA  [PW0016A_L]  (hidden comment: TPL7407LPWR)
U27  SN74LVC1G17DBVR  [DBV0005A_N]  (parts A,B of 2)
U28  TLV9001IDBV  [DBV0005A_N]

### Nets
3.3V: C147.1 C148.1 C149.1 U25.5(VCC) U27.5(VCC) U28.5(V+)
5V: R145.1 R149.1
12V: R148.2
GND: C144.1 C145.2 C146.1 C147.2 C148.2 C149.2 D33.2(A) D34.2(A) D35.2(GND) J22.1 J23.1 R147.1 R151.1 R153.1 U25.3(GND) U26.8(GND) U27.3(GND) U28.2(V-)
ANALOG_IN_1: D35.1(IO) J22.2 R152.2
DIG_IN_1: J21.2 R145.2 R146.1 R147.2
DIG_IN_2: J21.1 R149.2 R150.1 R151.2
DIG_OUT_1: J20.3 R148.1 U26.16(OUT1)
DIG_OUT_2: J20.2 U26.13(OUT4) U26.14(OUT3) U26.15(OUT2)
DIG_OUT_3: J20.1 U26.10(OUT7) U26.11(OUT6) U26.12(OUT5)
DIG_OUT_COM: C145.1 J23.2 U26.9(COM)
MSP_ADC_IN_3: U28.1(OUT) U28.4(IN-) ; off-sheet MSP_ADC_IN_3
MSP_IO_IN_1: TP54.1 U25.4(Y) ; off-sheet MSP_IO_IN_1
MSP_IO_IN_2: TP56.1 U27.4(Y) ; off-sheet MSP_IO_IN_2
MSP_IO_OUT_1: U26.1(IN1) ; off-sheet MSP_IO_OUT_1
MSP_IO_OUT_2: U26.2(IN2) U26.3(IN3) U26.4(IN4) ; off-sheet MSP_IO_OUT_2
MSP_IO_OUT_3: U26.5(IN5) U26.6(IN6) U26.7(IN7) ; off-sheet MSP_IO_OUT_3
NetC144_2: C144.2 D33.1(K) R146.2 TP53.1 U25.2(A)
NetC146_2: C146.2 D34.1(K) R150.2 TP55.1 U27.2(A)
NetR152_1: R152.1 R153.2 TP57.1 U28.3(IN+)

Not connected (* = marked no-connect by the designer): U25 1(NC)*; U27 1(NC)*

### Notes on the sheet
- Digital Input - 24V / 12V Input
- Positive-going input threshold voltage:   3.4V (-> 1.7V)
  Negative-going input threshold voltage:  2.2V (-> 1.1V)
- Digital Output - Open Collector
- Output 1:		Logic Output, High = 12V / Low = 0.4V
  Output 2 / 3: 	Low Side switch, max. 2A total
  Connect COM to VSupply (8.5V - 40V)
- 5.5V tolerant input
- Analog Input - 0V - 12V Input

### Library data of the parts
C144 C146 = CMP-0006196-2: CAP, CERM, 100 pF, 50 V, +/- 1%, C0G/NP0, 0402; Manufacturer: AVX; TaMin_C: -55°C; Polarized: N; SizeAreaWB_mm2: 3; Value1: Unknown; U/M: EA; Value: 100pF; TaMax_C: 125°C; SizeZ_mm: 0.6; SizeX_mm: 1; SizeY_mm: 0.5; Value2: 50V; AEC Category: Q200
C145 C147-C149 = CMP-0860555-1: as C123-C125 on sheet PROC219_PluckLock
D33 D34 = CMP-0005899-4: Diode, Zener, 5.1 V, 300 mW, SOD-523; Manufacturer: Diodes Inc.; Power_W: 300mW; Value1: 0.3W; SizeZ_mm: 0.65; AEC Category: Q101; SizeX_mm: 1.7; RJA_CperW: 417; SizeArea_mm2: 1.53; SizeY_mm: 0.9; SizeAreaWB_mm2: 5.13
D35 = CMP-0125981-1: 23V Clamp 18A (8/20µs) Ipp Tvs Diode Surface Mount SOD-323; Manufacturer: Texas Instruments; AEC Qualified: No; SizeZ_mm: 1mm; VRWM: 12V; Ppk: 300W; Breakdown Voltage: 12.7V; Cap_F: 12pF; Direction: Unidirectional; Number Of Channels: 1; Standoff Height: 0mm; TaMax_C: +150°C; TaMin_C: -55°C
J20 = CMP-0124724-1: as J13 on sheet PROC219_PluckLock
J21-J23 = CMP-0093089-2: 2 Position Wire to Board Terminal Block Horizontal with Board 0.138" (3.50mm) Through Hole; Manufacturer: Wurth; ContactFinish: Tin,Nickel; AEC Qualified: No; Max Wire Gauge: 16; Voltage_V: 300V; SizeZ_mm: 9.2mm; Current_A: 10A; DUT-Pitch_mm: 3.5mm; Min Wire Gauge: 30; Conn Gender: Female; Row_Count: 1; Is Female: yes
R145-R147 R149-R151 = CMP-0026658-1: as R110-R112 on sheet PROC219_PluckLock
R148 = CMP-0026700-1: as R123 on sheet PROC219_Serial
R152 = CMP-0065360-1: as R121 on sheet PROC219_Temp_Sense
R153 = CMP-0026333-2: RES, 3.32 k, 1%, 0.063 W, AEC-Q200 Grade 0, 0402; Manufacturer: Vishay-Dale; Power_W: 63mW; TempCo: 100 ppm/C; Value_Code: 3k32; Value: 3.32k; EIA_Code: E96; SizeX_mm: 1; SizeY_mm: 0.5; SizeZ_mm: 0.6; Value2: 0.063W; AEC Qualified: Y; VDC_V: 50V; AEC Category: Q200; AEC Grade: 0
TP53-TP57 = CMP-0003825-1: 1mm Test Point, SMT; Manufacturer: Any
U25 U27 = CMP-0051702-2: Single Schmitt-Trigger Buffer, DBV0005A, LARGE T&R; Manufacturer: Texas Instruments; Output Drive (IOL/IOH)(Max)(mA): 32/-32; Technology Family: LVC; ICC @ Nom Voltage(Max)(mA): 0.01; VCC(Min)(V): 1.65; F @ Nom Voltage(Max)(Mhz): 150; Schmitt Trigger: Yes; Voltage(Nom)(V): 1.8,2.5,3.3,5; 3-State Output: No; Bits(#): 1; VCC(Max)(V): 5.5; Input Type: CMOS/TTL; Logic: True; tpd @ Nom Voltage(Max)(ns): 11,6.5,5.5,5; Output Type: CMOS; Rating: Catalog; Sub-Family: Non-Inverting Buffer/Driver; AEC Category: Q200; AEC Qualified: N; CompType: IC; SizeX_mm: 2.8; SizeY_mm: 2.9; SizeZ_mm: 1.45
U26 = CMP-0033666-1: 7-Channel Low Side Driver, 0 to 40 V VOUT, -40 to 125 degC, 16-Pin TSSOP (PW), RoHS, Tape and Reel; Packing: TRUE; VCOM Min: 8.5 V; VOUT Min: 0 V; VOUT Max: 40 V; CI: 5 pF
U28 = CMP-0081549-1: Low-Power, Rail-to-Rail In and Out, 1-MHz Operational Amplifier, DBV0005A (SOT-23-5); Alternate Manufacturer: Texas Instruments; SizeAreaWB_mm2: 14.82; SizeZ_mm: 1.45; SizeX_mm: 2.8; SizeY_mm: 2.9; SizeArea_mm2: 8.12; CompType: IC; AEC Qualified: N; AEC Category: Q200

## Sheet PROC219_XDS110_Debug.SchDoc
size 431 x 279 mm; Date: Not shown in title block; ApprovedBy: Not shown in title block; CheckedBy: Not shown in title block; Author: Not shown in title block; CompanyName: Not shown in title block; Engineer: Not shown in title block; Organization: Not shown in title block; Address1: Not shown in title block; Address2: Not shown in title block; Address3: Not shown in title block; Address4: Not shown in title block; DocumentNumber: 1; Revision: Use project parameter SCH_Rev; SheetNumber: 14; SheetTotal: 16; PageSetup: Record=PageOptions¦CenterHorizontal=True¦CenterVertical=True¦PrintScale=1.00¦XCorrection=1.00¦YCorrection=1.00¦PrintKind=0¦BorderSize=5000000¦LeftOffset=0¦BottomOffset=0¦Orientation=2¦PaperLength=1000¦PaperWidth=1000¦Scale=100¦PaperSource=15¦PrintQuality=600¦MediaType=1¦DitherType=10¦PaperKind=Letter¦PrintScaleMode=1
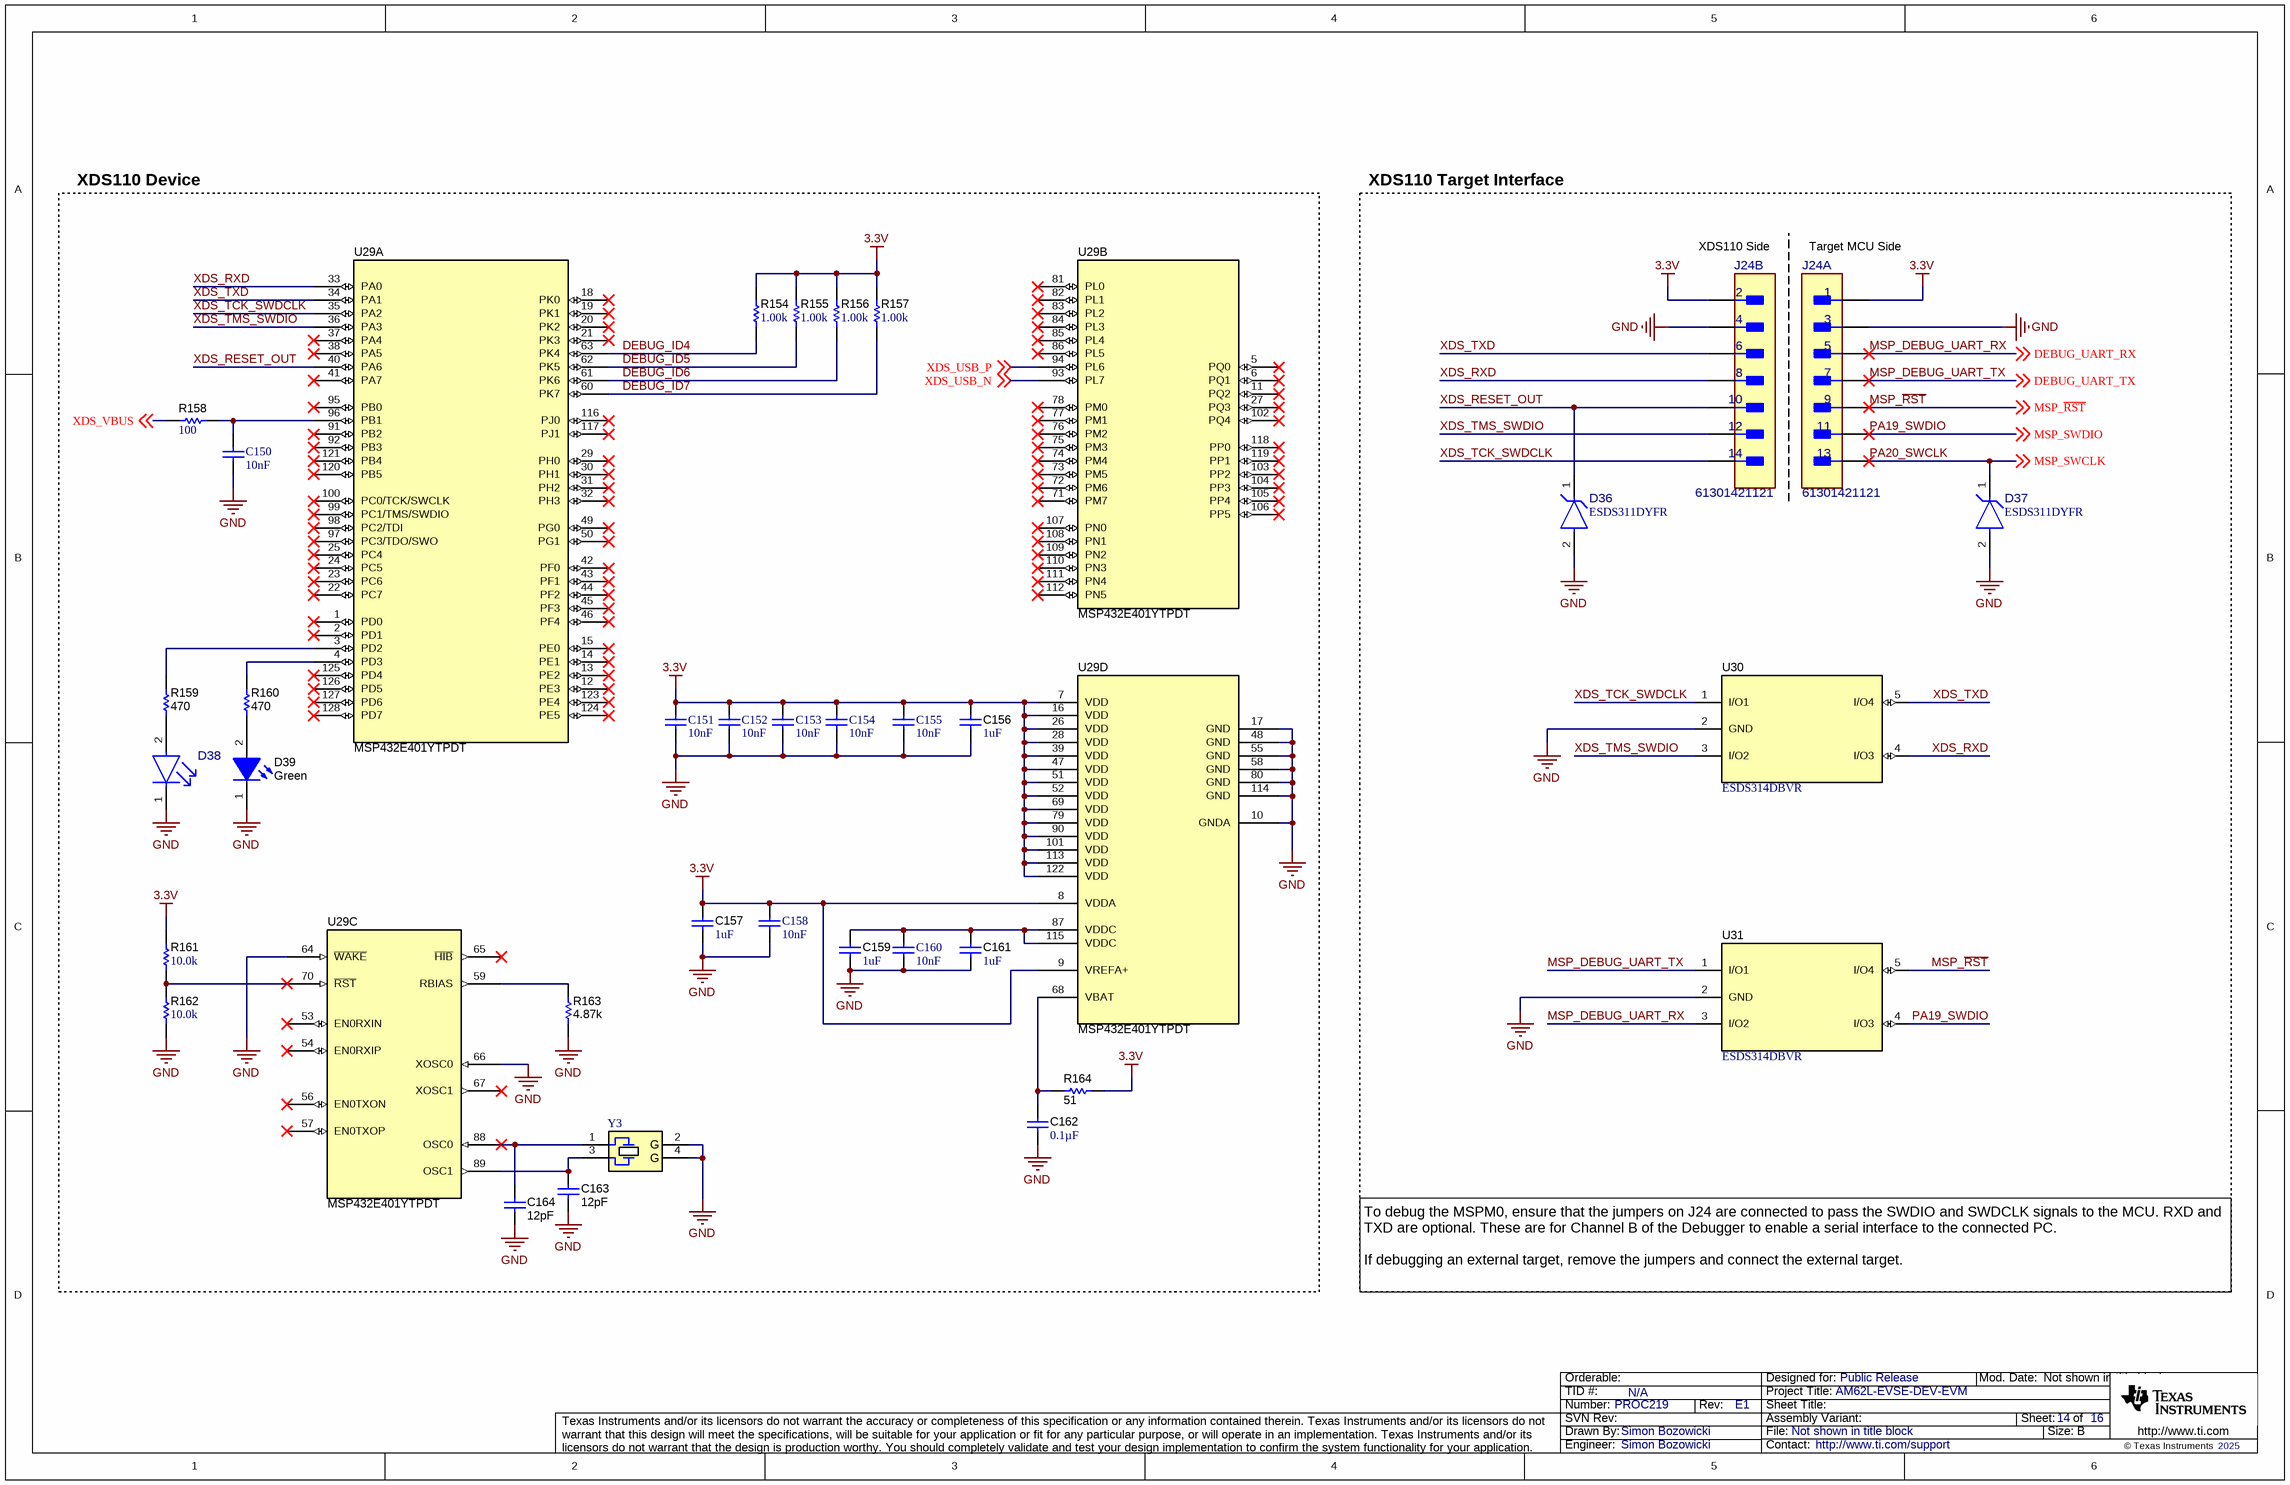
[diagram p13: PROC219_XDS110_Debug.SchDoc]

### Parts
C150  value 10nF  [WCAP-CSGP_0402_L1W0.5H0.5]  (hidden comment: 885012205050)
C151  value 10nF  [WCAP-CSGP_0402_L1W0.5H0.5]  (hidden comment: 885012205050)
C152  value 10nF  [WCAP-CSGP_0402_L1W0.5H0.5]  (hidden comment: 885012205050)
C153  value 10nF  [WCAP-CSGP_0402_L1W0.5H0.5]  (hidden comment: 885012205050)
C154  value 10nF  [WCAP-CSGP_0402_L1W0.5H0.5]  (hidden comment: 885012205050)
C155  value 10nF  [WCAP-CSGP_0402_L1W0.5H0.5]  (hidden comment: 885012205050)
C156  ValueDisplayed: 1uF  [0402]  (hidden comment: C1005X7S1A105K050BC)
C157  ValueDisplayed: 1uF  [0402]  (hidden comment: C1005X7S1A105K050BC)
C158  value 10nF  [WCAP-CSGP_0402_L1W0.5H0.5]  (hidden comment: 885012205050)
C159  ValueDisplayed: 1uF  [0402]  (hidden comment: C1005X7S1A105K050BC)
C160  value 10nF  [WCAP-CSGP_0402_L1W0.5H0.5]  (hidden comment: 885012205050)
C161  ValueDisplayed: 1uF  [0402]  (hidden comment: C1005X7S1A105K050BC)
C162  ValueDisplayed: 0.1µF  [0402]  (hidden comment: CC0402KRX7R8BB104)
C163  ValueDisplayed: 12pF  [0402]  (hidden comment: GRM1555C1H120JA01D)
C164  ValueDisplayed: 12pF  [0402]  (hidden comment: GRM1555C1H120JA01D)
D36  ESDS311DYFR  [DYF0002A-MFG]
D37  ESDS311DYFR  [DYF0002A-MFG]
D38  150060AS75000  [FP-150060AS75000_0603-MFG]  (value not drawn)
D39  value Green  [WL-SMCW_GREEN]  (hidden comment: 150060VS75000)
J24  61301421121  [FP-61301421121_HDR14-MFG]  (parts A,B of 2)
R154  ValueDisplayed: 1.00k  [0402]  (hidden comment: RC0402FR-071KL)
R155  ValueDisplayed: 1.00k  [0402]  (hidden comment: RC0402FR-071KL)
R156  ValueDisplayed: 1.00k  [0402]  (hidden comment: RC0402FR-071KL)
R157  ValueDisplayed: 1.00k  [0402]  (hidden comment: RC0402FR-071KL)
R158  ValueDisplayed: 100  [0402]  (hidden comment: ERJ-2RKF1000X)
R159  ValueDisplayed: 470  [0402]  (hidden comment: RC0402FR-07470RL)
R160  ValueDisplayed: 470  [0402]  (hidden comment: RC0402FR-07470RL)
R161  ValueDisplayed: 10.0k  [0402]  (hidden comment: ERJ-2RKF1002X)
R162  ValueDisplayed: 10.0k  [0402]  (hidden comment: ERJ-2RKF1002X)
R163  ValueDisplayed: 4.87k  [0402]  (hidden comment: CRCW04024K87FKED)
R164  ValueDisplayed: 51  [0402]  (hidden comment: CRCW040251R0JNED)
U29  MSP432E401YTPDT  [PDT0128A]  (parts A,B,C,D of 4)
U30  ESDS314DBVR  [DBV0005A_N]
U31  ESDS314DBVR  [DBV0005A_N]
Y3  NX3225GA-16.000M-STD-CRG-1  [NDK_NX3225GA]  (value not drawn)

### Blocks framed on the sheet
XDS110 Device: C150-C164 D38 D39 R154-R164 U29 Y3
XDS110 Target Interface: D36 D37 J24 U30 U31

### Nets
3.3V: C151.2 C152.2 C153.2 C154.2 C155.2 C156.1 C157.1 C158.2 J24.1 J24.2 R154.2 R155.2 R156.2 R157.2 R161.2 R164.2 U29.7(VDD) U29.8(VDDA) U29.9(VREFA+) U29.16(VDD) U29.26(VDD) U29.28(VDD) U29.39(VDD) U29.47(VDD) U29.51(VDD) U29.52(VDD) U29.69(VDD) U29.79(VDD) U29.90(VDD) U29.101(VDD) U29.113(VDD) U29.122(VDD)
GND: C150.1 C151.1 C152.1 C153.1 C154.1 C155.1 C156.2 C157.2 C158.1 C159.2 C160.1 C161.2 C162.1 C163.2 C164.2 D36.2(GND) D37.2(GND) D38.1(CATHODE) D39.1(K) J24.3 J24.4 R162.1 R163.1 U29.10(GNDA) U29.17(GND) U29.48(GND) U29.55(GND) U29.58(GND) U29.64(~{WAKE}) U29.66(XOSC0) U29.80(GND) U29.114(GND) U30.2(GND) U31.2(GND) Y3.2(GND) Y3.4(GND)
DEBUG_ID4: R154.1 U29.63(PK4)
DEBUG_ID5: R155.1 U29.62(PK5)
DEBUG_ID6: R156.1 U29.61(PK6)
DEBUG_ID7: R157.1 U29.60(PK7)
MSP_DEBUG_UART_RX: J24.5 U31.3(I/O2) ; off-sheet DEBUG_UART_RX  [also labelled DEBUG_UART_RX]
MSP_DEBUG_UART_TX: J24.7 U31.1(I/O1) ; off-sheet DEBUG_UART_TX  [also labelled DEBUG_UART_TX]
MSP_~{RST}: J24.9 U31.5(I/O4) ; off-sheet MSP_~{RST}
PA19_SWDIO: J24.11 U31.4(I/O3) ; off-sheet MSP_SWDIO  [also labelled MSP_SWDIO]
PA20_SWCLK: D37.1(I/O) J24.13 ; off-sheet MSP_SWCLK  [also labelled MSP_SWCLK]
XDS_RESET_OUT: D36.1(I/O) J24.10 U29.40(PA6)
XDS_RXD: J24.8 U29.33(PA0) U30.4(I/O3)
XDS_TCK_SWDCLK: J24.14 U29.35(PA2) U30.1(I/O1)
XDS_TMS_SWDIO: J24.12 U29.36(PA3) U30.3(I/O2)
XDS_TXD: J24.6 U29.34(PA1) U30.5(I/O4)
XDS_USB_N: U29.93(PL7) ; off-sheet XDS_USB_N
XDS_USB_P: U29.94(PL6) ; off-sheet XDS_USB_P
XDS_VBUS: R158.1 ; off-sheet XDS_VBUS
NetC150_2: C150.2 R158.2 U29.96(PB1)
NetC159_1: C159.1 C160.2 C161.1 U29.87(VDDC) U29.115(VDDC)
NetC162_2: C162.2 R164.1 U29.68(VBAT)
NetC163_1: C163.1 U29.89(OSC1) Y3.3
NetC164_1: C164.1 U29.88(OSC0) Y3.1
NetD38_2: D38.2(ANODE) R159.1
NetD39_2: D39.2(A) R160.1
NetR159_2: R159.2 U29.3(PD2)
NetR160_2: R160.2 U29.4(PD3)
NetR161_1: R161.1 R162.2 U29.70(~{RST})
NetR163_2: R163.2 U29.59(RBIAS)

Not connected (* = marked no-connect by the designer): U29 1(PD0)* 2(PD1)* 5(PQ0)* 6(PQ1)* 11(PQ2)* 12(PE3)* 13(PE2)* 14(PE1)* 15(PE0)* 18(PK0)* 19(PK1)* 20(PK2)* 21(PK3)* 22(PC7)* 23(PC6)* 24(PC5)* 25(PC4)* 27(PQ3)* 29(PH0)* 30(PH1)* 31(PH2)* 32(PH3)* 37(PA4)* 38(PA5)* 41(PA7)* 42(PF0)* 43(PF1)* 44(PF2)* 45(PF3)* 46(PF4)* 49(PG0)* 50(PG1)* 53(EN0RXIN)* 54(EN0RXIP)* 56(EN0TXON)* 57(EN0TXOP)* 65(~{HIB})* 67(XOSC1)* 71(PM7)* 72(PM6)* 73(PM5)* 74(PM4)* 75(PM3)* 76(PM2)* 77(PM1)* 78(PM0)* 81(PL0)* 82(PL1)* 83(PL2)* 84(PL3)* 85(PL4)* 86(PL5)* 91(PB2)* 92(PB3)* 95(PB0)* 97(PC3/TDO/SWO)* 98(PC2/TDI)* 99(PC1/TMS/SWDIO)* 100(PC0/TCK/SWCLK)* 102(PQ4)* 103(PP2)* 104(PP3)* 105(PP4)* 106(PP5)* 107(PN0)* 108(PN1)* 109(PN2)* 110(PN3)* 111(PN4)* 112(PN5)* 116(PJ0)* 117(PJ1)* 118(PP0)* 119(PP1)* 120(PB5)* 121(PB4)* 123(PE4)* 124(PE5)* 125(PD4)* 126(PD5)* 127(PD6)* 128(PD7)*

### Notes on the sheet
- (near J24) XDS110 Side
- (near J24) Target MCU Side
- To debug the MSPM0, ensure that the jumpers on J24 are connected to pass the SWDIO and SWDCLK signals to the MCU. RXD and TXD are optional. These are for Channel B of the Debugger to enable a serial interface to the connected PC.
  If debugging an external target, remove the jumpers and connect the external target.

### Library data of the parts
C150-C155 C158 C160 = CMP-0052806-1: WCAP-CSGP Multilayer Ceramic Chip Capacitor, General Purpose, size 0402, X7R, 10nF, 25VDC; Manufacturer: Wurth Elektronik; Capacitance Tolerance: +/-10%; Dissipation Factor: 3.5%; Insulation Resistance: 10GOhm; Rated Voltage (DC): 25V; Technical Reference: X7R0402103K025DFCT10000
C156 C157 C159 C161 = CMP-0006300-2: CAP, CERM, 1 uF, 10 V, +/- 10%, X7S, 0402; Manufacturer: TDK; TaMin_C: -55°C; ESR_ohm: 0.011416; Polarized: N; SizeAreaWB_mm2: 3; Value1: 0.011416 ohm; U/M: EA; Value: 1uF; TaMax_C: 125°C; SizeZ_mm: 0.6; SizeX_mm: 1; SizeY_mm: 0.5; Value2: 10V; Cap_F: 1µF; IRMS_A: 1.483A; AEC Category: Q200
C162 = CMP-0860555-1: as C123-C125 on sheet PROC219_PluckLock
C163 C164 = CMP-0006415-2: CAP, CERM, 12 pF, 50 V, +/- 5%, C0G/NP0, 0402; Manufacturer: MuRata; TaMin_C: -55°C; Polarized: N; SizeAreaWB_mm2: 3; Value1: Unknown; U/M: EA; Value: 12pF; TaMax_C: 125°C; SizeZ_mm: 0.6; SizeX_mm: 1; SizeY_mm: 0.5; Value2: 50V; AEC Category: Q200
D36 D37 = CMP-0122929-1: as D26 on sheet PROC219_PluckLock
D38 = CMP-0124839-1: Amber 605nm LED Indication - Discrete 2V 0603 (1608 Metric); Manufacturer: Wurth Electronics; Angle: 140°; LambdaP: 610nm; Power_TotalModule: 72mW; SizeZ_mm: 0.8mm; Tjmax_C: 95°C; Vr_V: 5V; AEC Qualified: No; Forward Current: 20mA; Led Orientation: Top View; Luminous Intensity: 130mcd
D39 = CMP-0002894-2: as D27 on sheet PROC219_PluckLock
J24 = CMP-0097334-1: Connector Header Through Hole 14 position 0.100" (2.54mm); Manufacturer: Wurth Electronics; AEC Qualified: No; Conn Gender: Male; Current_A: 3A; Voltage_V: 250V; ContactFinish: Gold; Row_Count: 2; SizeZ_mm: 8.89mm; Conn Orientation: Straight
R154-R157 = CMP-0026725-1: as R108 on sheet PROC219_PluckLock
R158 = CMP-0026656-1: RES, 100, 1%, 0.1 W, 0402; Manufacturer: Panasonic; Power_W: 100mW; TempCo: 100 ppm/C; Value_Code: 100R; U/M: EA; Value: 100; EIA_Code: E96; SizeX_mm: 1; SizeY_mm: 0.5; SizeZ_mm: 0.6; Value2: 0.1W; VDC_V: 50V; AEC Category: Q200
R159 R160 = CMP-0026736-1: RES, 470, 1%, 0.063 W, 0402; Manufacturer: Yageo America; Power_W: 63mW; TempCo: 100 ppm/C; Value_Code: 470R; U/M: EA; Value: 470; SizeX_mm: 1; SizeY_mm: 0.5; SizeZ_mm: 0.6; Value2: 0.063W; AEC Qualified: N; VDC_V: 50V; AEC Category: Q200
R161 R162 = CMP-0026658-1: as R110-R112 on sheet PROC219_PluckLock
R163 = CMP-0026413-2: RES, 4.87 k, 1%, 0.063 W, AEC-Q200 Grade 0, 0402; Manufacturer: Vishay-Dale; Value: 4.87k; Value_Code: 4k87; Power_W: 63mW; Value2: 0.063W; VDC_V: 50V; TempCo: 100 ppm/C; SizeArea_mm2: 0.5; SizeX_mm: 1; SizeZ_mm: 0.6; EIA_Code: E96; AEC Category: Q200; AEC Qualified: Y; AEC Grade: 0
R164 = CMP-0026946-3: RES, 51, 5%, 0.063 W, AEC-Q200 Grade 0, 0402; Manufacturer: Vishay-Dale; Value: 51; Value_Code: 51R0; Power_W: 63mW; Value2: 0.063W; VDC_V: 50V; TempCo: 200 ppm/C; SizeArea_mm2: 0.5; SizeX_mm: 1; SizeZ_mm: 0.6; EIA_Code: E24; AEC Category: Q200; AEC Qualified: Y; AEC Grade: 0
U29 = CMP-0077953-1: MSP432E401YTPDT, PDT0128A (TQFP-128); Alternate PartNumber: MSP432E401YTPDTR; Alternate Manufacturer: Texas Instruments; SizeAreaWB_mm2: 324; SizeZ_mm: 1.2; SizeX_mm: 16; SizeArea_mm2: 256; CompType: IC; AEC Qualified: N; AEC Category: Q200
U30 U31 = CMP-0085635-1: Data-Line Surge and ESD Protection Diode Array, DBV0005A (SOT-23-5); Alternate Manufacturer: Texas Instruments; CompType: IC; SizeX_mm: 2.8; Rating: Catalog; AEC Category: Q200; SizeZ_mm: 1.45; SizeArea_mm2: 8.12; AEC Qualified: N; SizeAreaWB_mm2: 14.82; SizeY_mm: 2.9
Y3 = CMP-0004635-3: Crystal, 16 MHz, 8pF, SMD; Manufacturer: NDK; TaMin_C: -10°C; TaMax_C: 70°C; Frequency Stability: +/-30ppm; Frequency_Fixed: 16MHz

## Sheet PROC219_Connectors.SchDoc
size 431 x 279 mm; Date: Not shown in title block; ApprovedBy: Not shown in title block; CheckedBy: Not shown in title block; Author: Not shown in title block; CompanyName: Not shown in title block; Engineer: Not shown in title block; Organization: Not shown in title block; Address1: Not shown in title block; Address2: Not shown in title block; Address3: Not shown in title block; Address4: Not shown in title block; DocumentNumber: 2; Revision: Use project parameter SCH_Rev; SheetNumber: 15; SheetTotal: 16; PageSetup: Record=PageOptions¦CenterHorizontal=True¦CenterVertical=True¦PrintScale=1.00¦XCorrection=1.00¦YCorrection=1.00¦PrintKind=0¦BorderSize=5000000¦LeftOffset=0¦BottomOffset=0¦Orientation=2¦PaperLength=1000¦PaperWidth=1000¦Scale=100¦PaperSource=15¦PrintQuality=600¦MediaType=1¦DitherType=10¦PaperKind=Letter¦PrintScaleMode=1
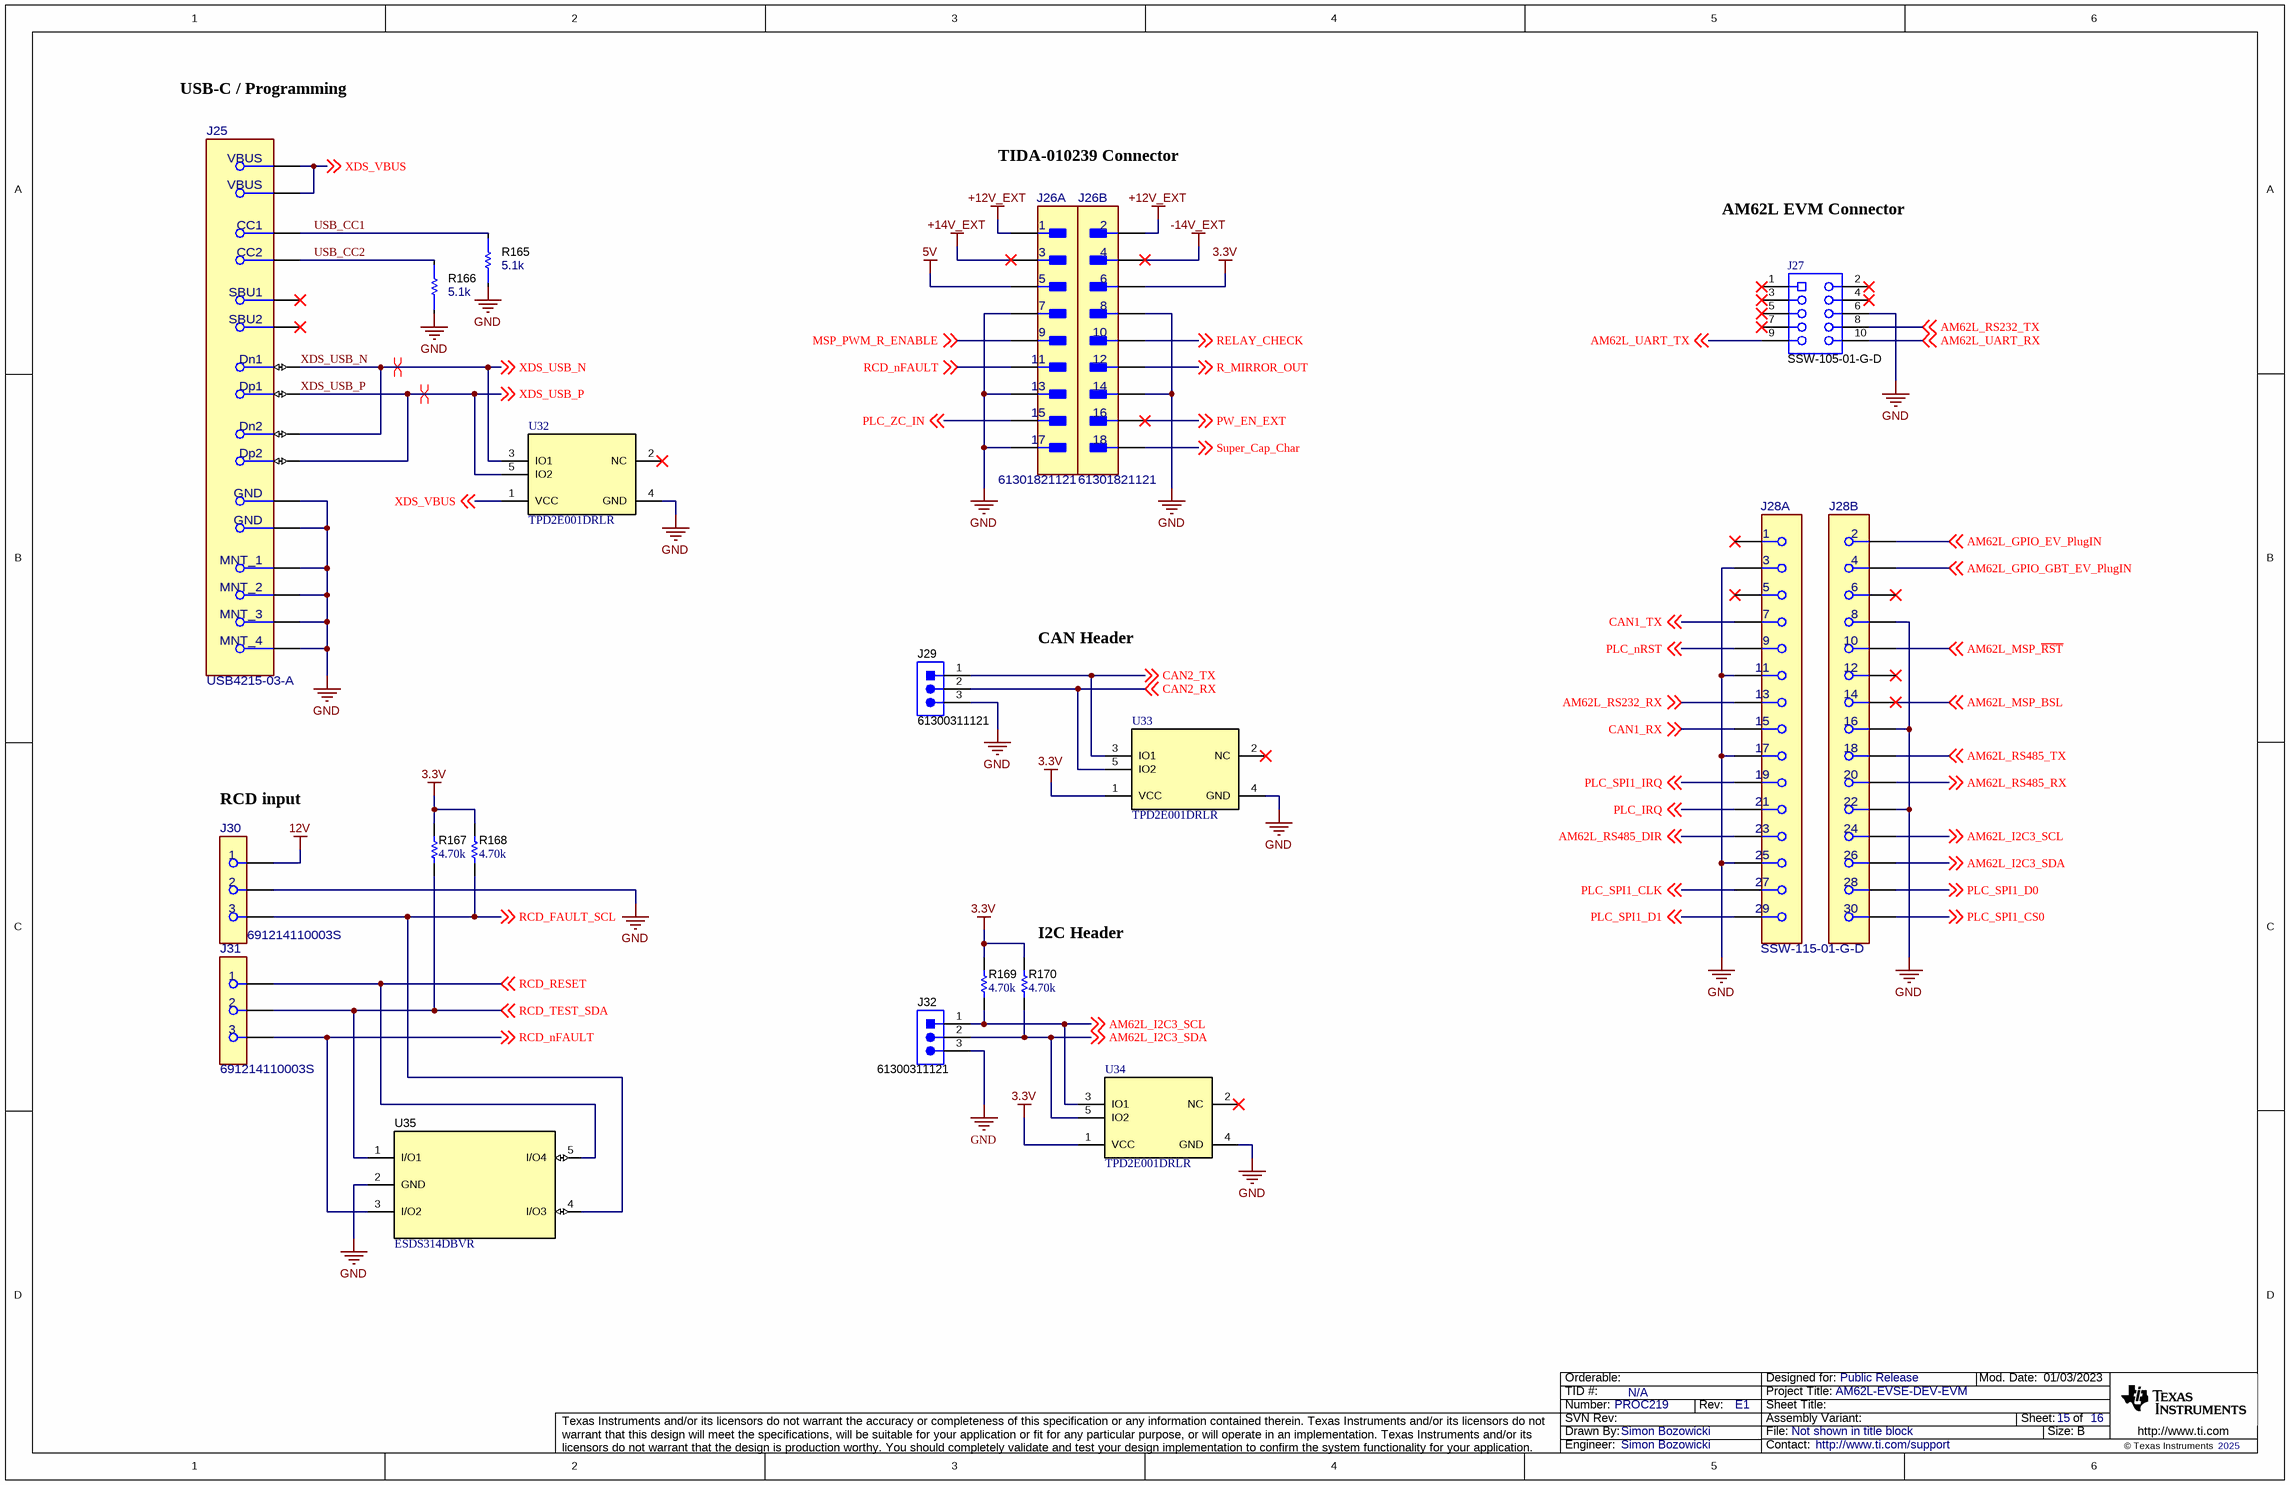
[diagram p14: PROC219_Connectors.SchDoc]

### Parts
J25  USB4215-03-A  [FP-USB4215-03-A_CONN_USB-MFG]
J26  61301821121  [FP-61301821121_HDR18-MFG]  (parts A,B of 2)
J27  SSW-105-01-G-D  [Samtec_SSW-105-01-x-D]
J28  SSW-115-01-G-D  [FP-SSW-115-01-G-D_CONN_RCPT30-MFG]  (parts A,B of 2)
J29  61300311121  [WURTH_61300311121]
J30  691214110003S  [FP-691214110003S_CONN_TERM_BLK_3-MFG]
J31  691214110003S  [FP-691214110003S_CONN_TERM_BLK_3-MFG]
J32  61300311121  [WURTH_61300311121]
R165  value 5.1k  [FP-RMCF0402FT5K10_0402-MFG]  (hidden comment: RMCF0402FT5K10)
R166  value 5.1k  [FP-RMCF0402FT5K10_0402-MFG]  (hidden comment: RMCF0402FT5K10)
R167  ValueDisplayed: 4.70k  [0402]  (hidden comment: ERJ-2RKF4701X)
R168  ValueDisplayed: 4.70k  [0402]  (hidden comment: ERJ-2RKF4701X)
R169  ValueDisplayed: 4.70k  [0402]  (hidden comment: ERJ-2RKF4701X)
R170  ValueDisplayed: 4.70k  [0402]  (hidden comment: ERJ-2RKF4701X)
U32  TPD2E001DRLR  [DRL0005A]
U33  TPD2E001DRLR  [DRL0005A]
U34  TPD2E001DRLR  [DRL0005A]
U35  ESDS314DBVR  [DBV0005A_N]

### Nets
3.3V: J26.6 R167.2 R168.2 R169.2 R170.2 U33.1(VCC) U34.1(VCC)
5V: J26.5
12V: J30.1
+12V_EXT: J26.1 J26.2
+14V_EXT: J26.3
-14V_EXT: J26.4
GND: J25.1(MNT_1) J25.2(MNT_2) J25.3(MNT_3) J25.4(MNT_4) J25.A1-B12(GND) J25.B1-A12(GND) J26.7 J26.8 J26.13 J26.14 J26.17 J27.6 J28.3 J28.8 J28.11 J28.16 J28.17 J28.22 J28.25 J29.3 J30.2 J32.3 R165.1 R166.1 U32.4(GND) U33.4(GND) U34.4(GND) U35.2(GND)
AM62L_GPIO_EV_PlugIN: J28.2 ; off-sheet AM62L_GPIO_EV_PlugIN
AM62L_GPIO_GBT_EV_PlugIN: J28.4 ; off-sheet AM62L_GPIO_GBT_EV_PlugIN
AM62L_I2C3_SCL: J28.24 J32.1 R169.1 U34.3(IO1) ; off-sheet AM62L_I2C3_SCL
AM62L_I2C3_SDA: J28.26 J32.2 R170.1 U34.5(IO2) ; off-sheet AM62L_I2C3_SDA
AM62L_MSP_BSL: J28.14 ; off-sheet AM62L_MSP_BSL
AM62L_MSP_~{RST}: J28.10 ; off-sheet AM62L_MSP_~{RST}
AM62L_RS232_RX: J28.13 ; off-sheet AM62L_RS232_RX
AM62L_RS232_TX: J27.8 ; off-sheet AM62L_RS232_TX
AM62L_RS485_DIR: J28.23 ; off-sheet AM62L_RS485_DIR
AM62L_RS485_RX: J28.20 ; off-sheet AM62L_RS485_RX
AM62L_RS485_TX: J28.18 ; off-sheet AM62L_RS485_TX
AM62L_UART_RX: J27.10 ; off-sheet AM62L_UART_RX
AM62L_UART_TX: J27.9 ; off-sheet AM62L_UART_TX
CAN1_RX: J28.15 ; off-sheet CAN1_RX
CAN1_TX: J28.7 ; off-sheet CAN1_TX
CAN2_RX: J29.2 U33.5(IO2) ; off-sheet CAN2_RX
CAN2_TX: J29.1 U33.3(IO1) ; off-sheet CAN2_TX
MSP_PWM_R_ENABLE: J26.9 ; off-sheet MSP_PWM_R_ENABLE
PLC_IRQ: J28.21 ; off-sheet PLC_IRQ
PLC_nRST: J28.9 ; off-sheet PLC_nRST
PLC_SPI1_CLK: J28.27 ; off-sheet PLC_SPI1_CLK
PLC_SPI1_CS0: J28.30 ; off-sheet PLC_SPI1_CS0
PLC_SPI1_D0: J28.28 ; off-sheet PLC_SPI1_D0
PLC_SPI1_D1: J28.29 ; off-sheet PLC_SPI1_D1
PLC_SPI1_IRQ: J28.19 ; off-sheet PLC_SPI1_IRQ
PLC_ZC_IN: J26.15 ; off-sheet PLC_ZC_IN
PW_EN_EXT: J26.16 ; off-sheet PW_EN_EXT
R_MIRROR_OUT: J26.12 ; off-sheet R_MIRROR_OUT
RCD_FAULT_SCL: J30.3 R168.1 U35.4(I/O3) ; off-sheet RCD_FAULT_SCL
RCD_nFAULT: J26.11 J31.3 U35.3(I/O2) ; off-sheet RCD_nFAULT
RCD_RESET: J31.1 U35.5(I/O4) ; off-sheet RCD_RESET
RCD_TEST_SDA: J31.2 R167.1 U35.1(I/O1) ; off-sheet RCD_TEST_SDA
RELAY_CHECK: J26.10 ; off-sheet RELAY_CHECK
Super_Cap_Char: J26.18 ; off-sheet Super_Cap_Char
USB_CC1: J25.A5(CC1) R165.2
USB_CC2: J25.B5(CC2) R166.2
XDS_USB_N: J25.A7(Dn1) J25.B7(Dn2) U32.3(IO1) ; off-sheet XDS_USB_N
XDS_USB_P: J25.A6(Dp1) J25.B6(Dp2) U32.5(IO2) ; off-sheet XDS_USB_P
XDS_VBUS: J25.A4-B9(VBUS) J25.B4-A9(VBUS) U32.1(VCC) ; off-sheet XDS_VBUS

Not connected (* = marked no-connect by the designer): J25 A8(SBU1)* B8(SBU2)*; J27 1* 2* 3* 4* 5* 7*; J28 1* 5* 6* 12*; U32 2(NC)*; U33 2(NC)*; U34 2(NC)*

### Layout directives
differential pair: XDS_USB_N, XDS_USB_P

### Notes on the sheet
- USB-C / Programming
- TIDA-010239 Connector
- AM62L EVM Connector
- CAN Header
- RCD input
- (near R170) I2C Header

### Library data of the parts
J25 = CMP-0123499-1: USB-C (USB TYPE-C) USB 2.0 Receptacle Connector 24 (16+8 Dummy) Position Surface Mount, Right Angle; Through Hole; Manufacturer: GCT; ContactFinish: Gold,Nickel; Current_A: 5A; Shrouded: true; Voltage_V: 48V; AEC Qualified: No; DUT-Pitch_mm: 0.5mm; Is Female: yes; SizeZ_mm: 3.41mm; Usb Standard: USB 2.0
J26 = CMP-0124771-1: Connector Header Through Hole 18 position 0.100" (2.54mm); Manufacturer: Wurth; ContactFinish: Gold; Current_A: 3A; Row_Count: 2; Voltage_V: 250V; AEC Qualified: No; Conn Gender: Male; Conn Orientation: Vertical; SizeZ_mm: 8.89mm
J27 = CMP-0074852-1: Receptacle, 2.54mm, 5X2, Gold, TH; Manufacturer: Samtec; CNHeader: False; Current_A: 4.7A; Gender: Female; Cert_CSA: Y; Voltage_V: 465V; CompType: Socket Strip; Row_Count: 2; RowSpacing_mm: 2.54; CT: True
J28 = CMP-0126816-1: 30 Position Receptacle Connector 0.100" (2.54mm) Through Hole Gold; Manufacturer: Samtec; ContactFinish: Gold,Nickel; Current_A: 4.7A; Row_Count: 2; Voltage_V: 655V; AEC Qualified: No; Conn Gender: Female; Conn Orientation: Vertical; Is Female: yes; SizeZ_mm: 8.64mm
J29 J32 = CMP-0054796-4: Header, 2.54 mm, 3x1, Gold, TH; Manufacturer: Wurth Elektronik; Green_REACh: Passed; CT: FALSE; CNHeader: TRUE; Green_Lifecycle: Active
J30 J31 = CMP-0124724-1: as J13 on sheet PROC219_PluckLock
R165 R166 = CMP-0093159-1: 5.1kΩ ±1% 0.063W 0402 Thick Film Chip Resistor AEC-Q200 compliant; Manufacturer: Stackpole Electronics; Power_W: 63mW; TempCo: 100ppm/°C; VDC_V: 50V; SizeZ_mm: 0.35mm; AEC Qualified: Yes; AEC Grade: Grade 0
R167-R170 = CMP-0026700-1: as R123 on sheet PROC219_Serial
U32-U34 = CMP-0043096-2: Low-Capacitance + / - 15 kV ESD-Protection Array for High-Speed Data Interfaces, 2 Channels, -40 to +85 degC, 5-pin SOT (DRL), Green (RoHS & no Sb/Br); Manufacturer: Texas Instruments; IO Leakage Current(nA): 1; IO Capacitance(Typ)(pF): 1.5; USB High Speed: TRUE; SubFamily: ESD Solution; Breakdown Voltage(Min)(V): 11; IEC 61000-4-2 Air-Gap(+/- kV): 15; IEC 61000-4-2 Contact(+/- kV): 8
U35 = CMP-0085635-1: as U30 on sheet PROC219_XDS110_Debug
